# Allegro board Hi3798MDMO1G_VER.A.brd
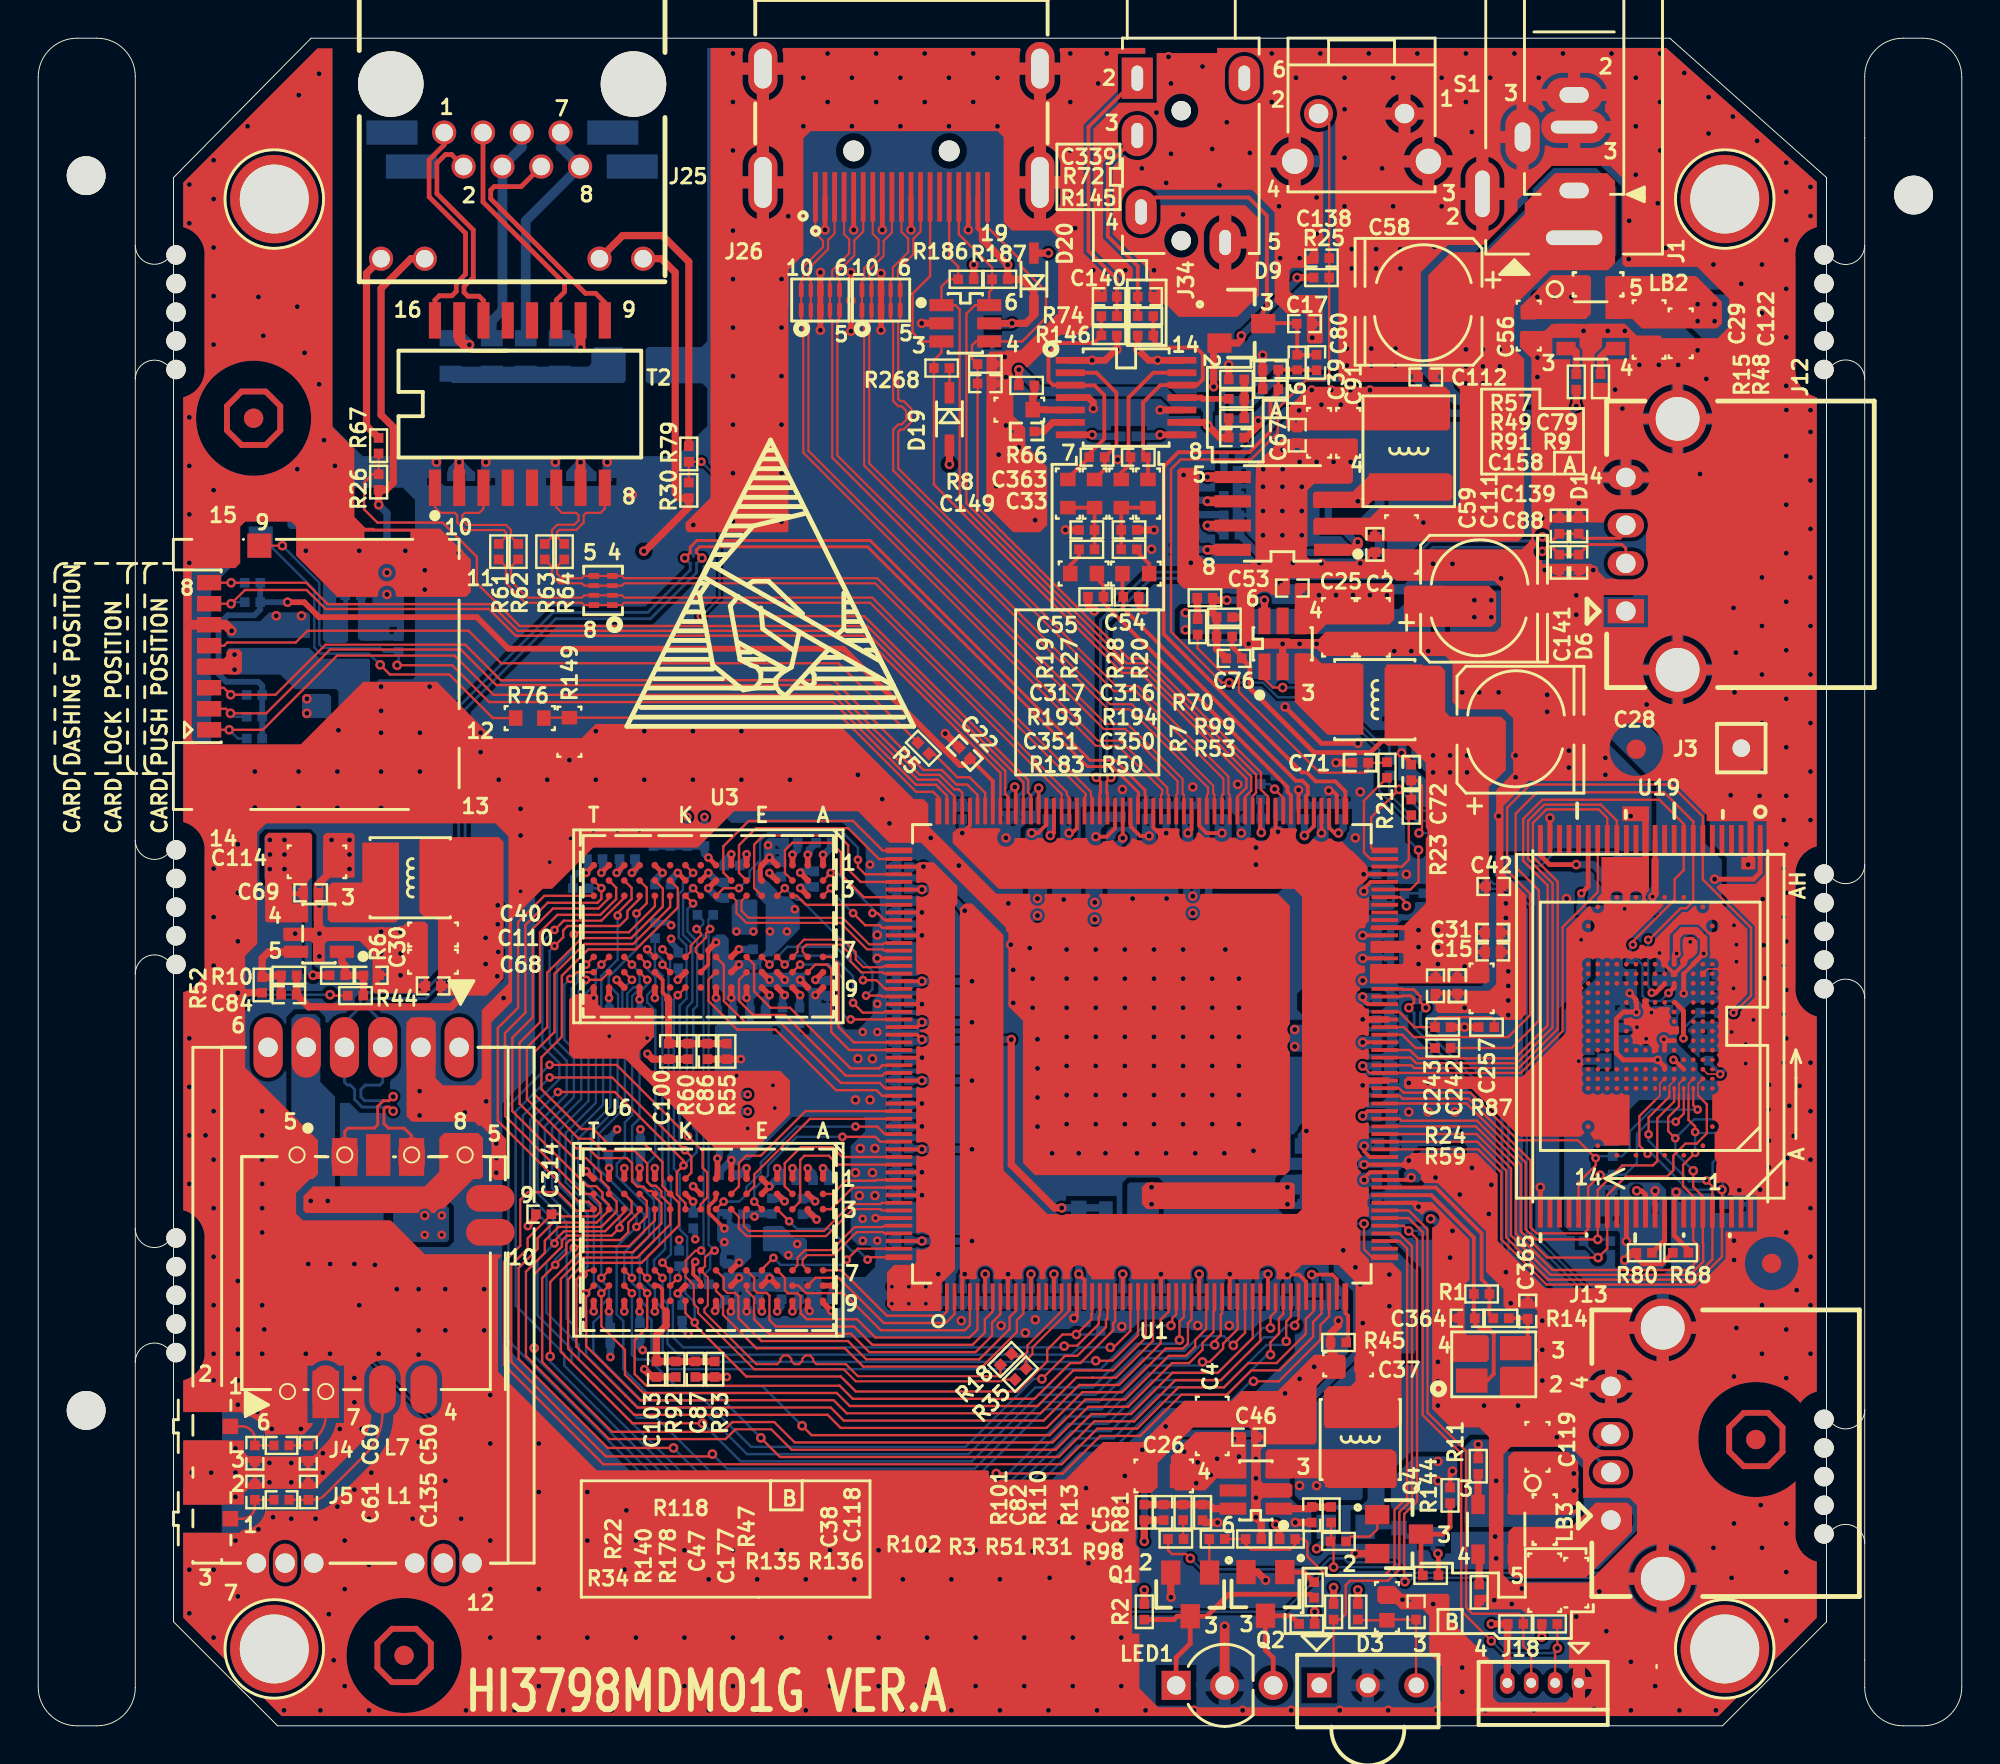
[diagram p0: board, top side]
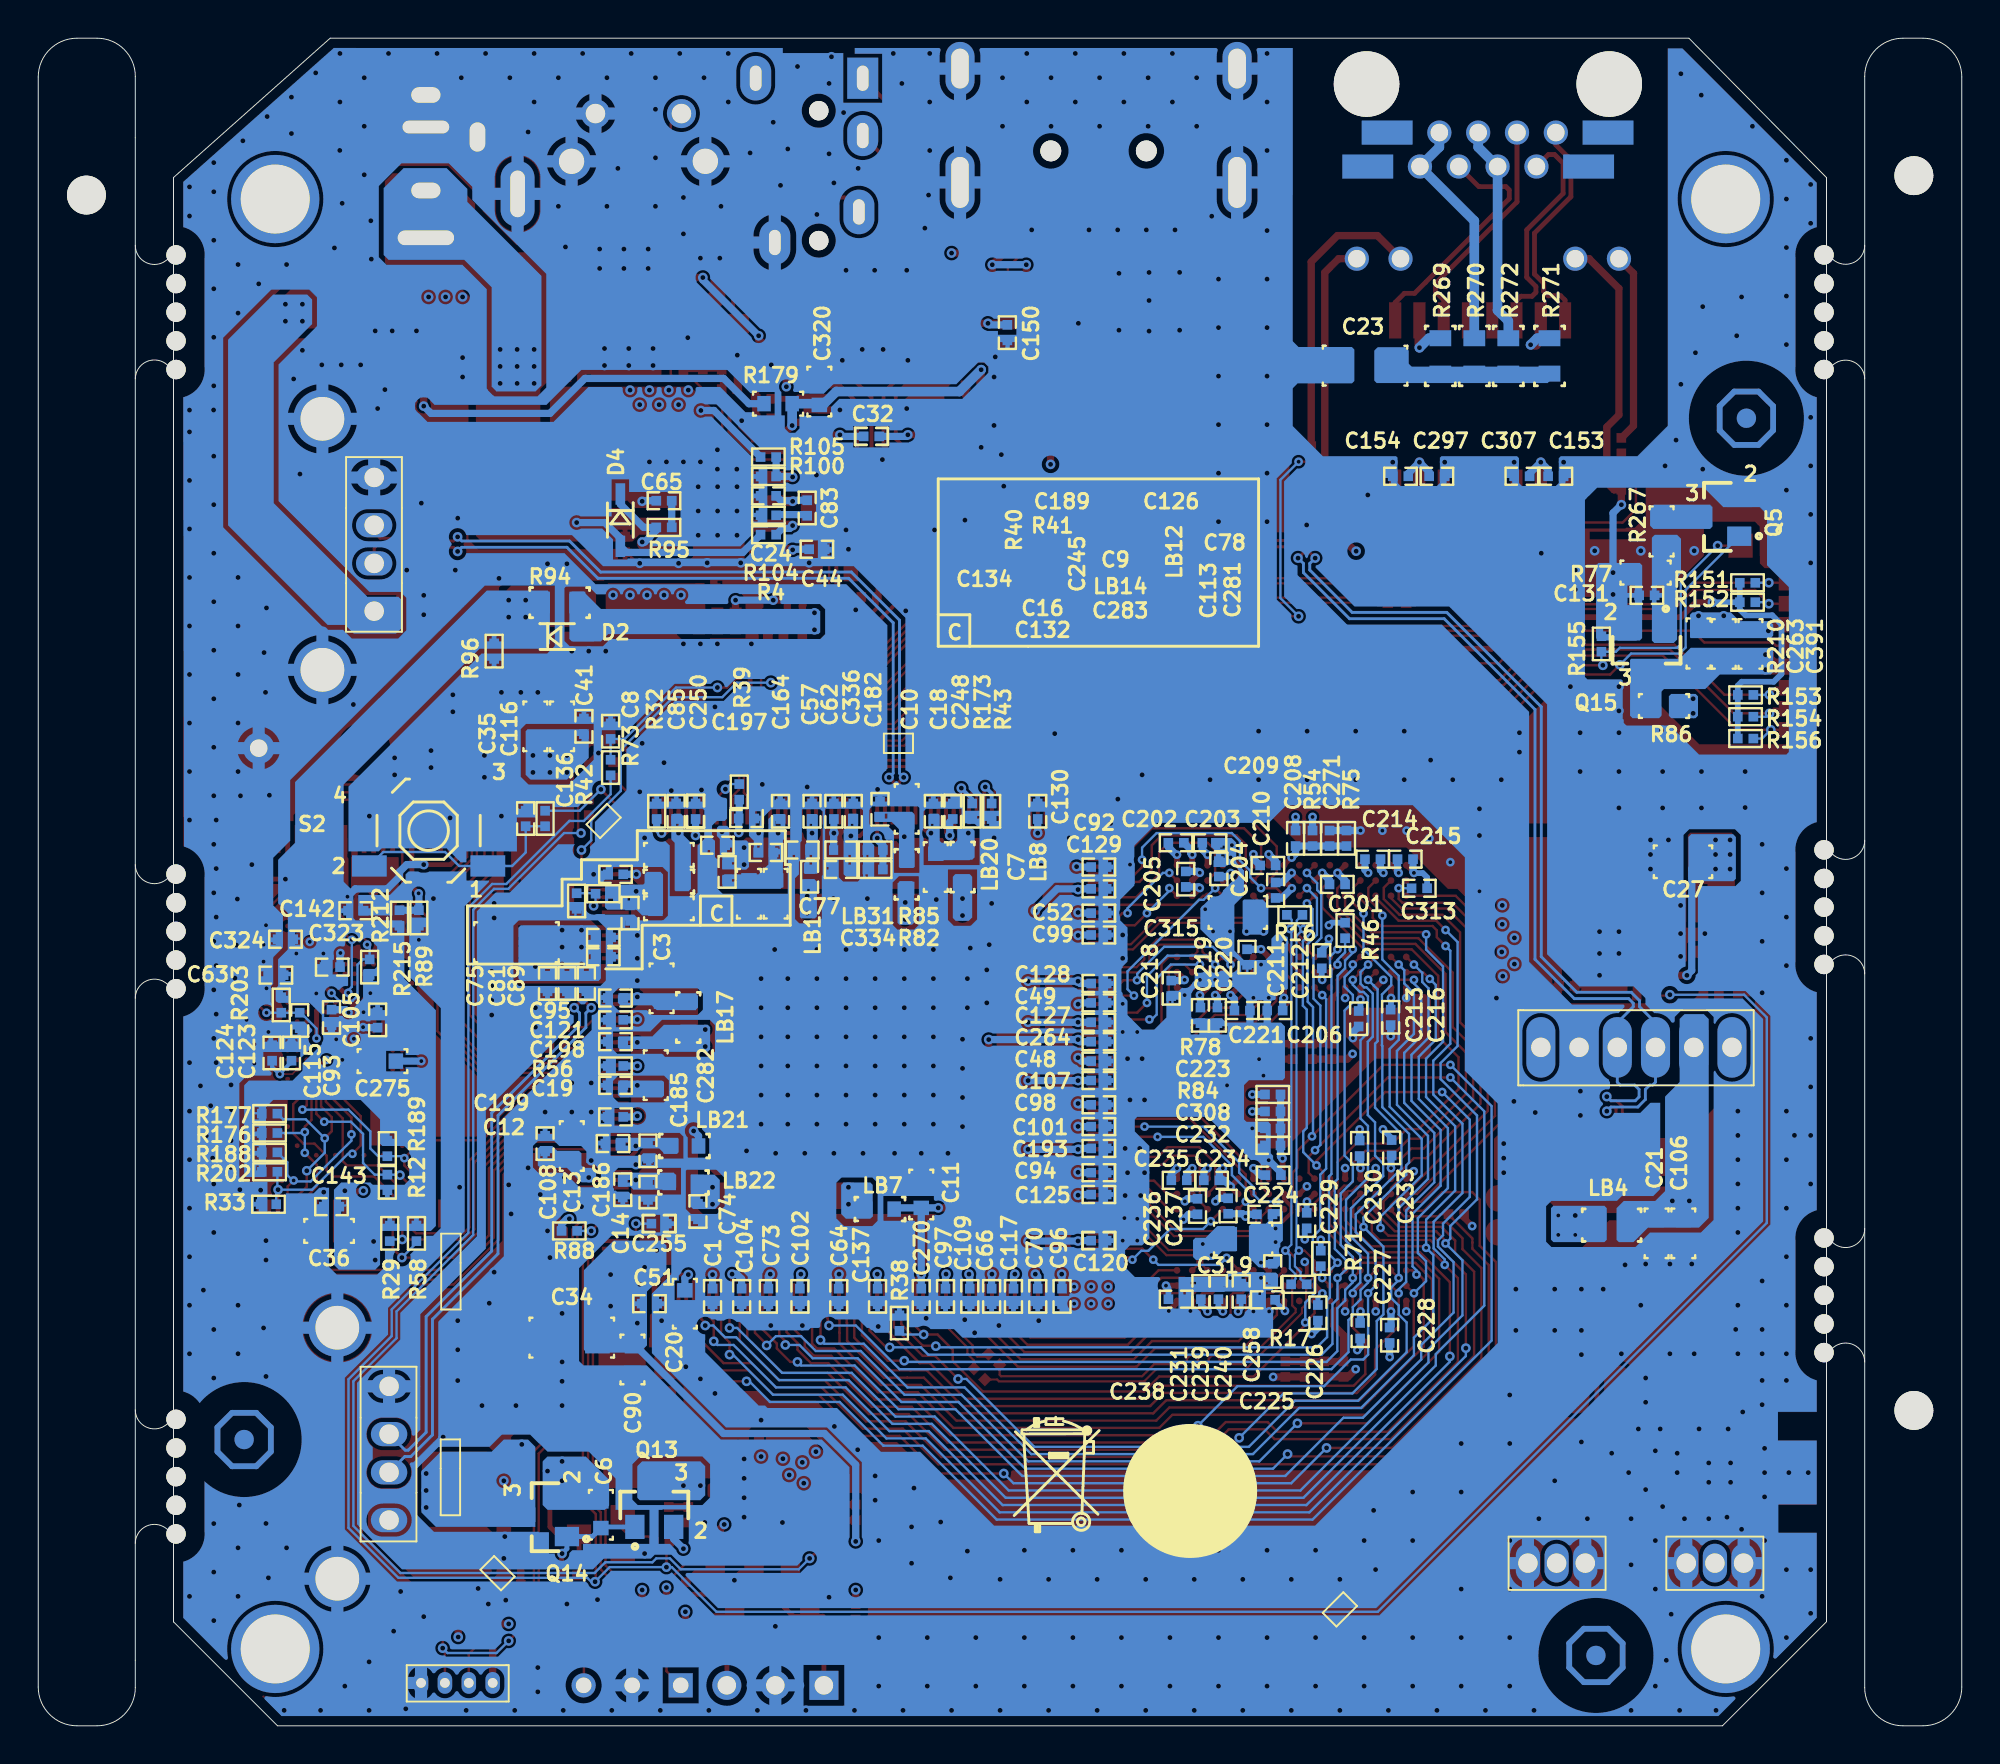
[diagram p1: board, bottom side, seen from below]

Outline 100.66 x 88.35 mm; copper layers: TOP, GND02, POWER03, BOTTOM. Coordinates in mm from the lower left corner of the outline.
Outline path: 0,86.32 0,2.03 arc(0.6,0.6) 2.03,0 3.08,0 arc(4.49,0.59) 5.08,2 5.08,86.35 arc(4.49,87.76) 3.08,88.35 2.03,88.35 arc(0.6,87.75) 0,86.32 ; 7.08,81.05 14.28,88.35 85.38,88.35 93.58,81.05 93.58,5.44 88.14,0 12.53,0 7.08,5.45 7.08,81.05 ; 95.58,86.35 95.58,2 arc(96.17,0.59) 97.58,0 98.63,0 arc(100.06,0.6) 100.66,2.03 100.66,86.32 arc(100.06,87.75) 98.63,88.35 97.58,88.35 arc(96.17,87.76) 95.58,86.35

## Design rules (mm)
constraint set DEFAULT: min track width 0.127
net group 01: nets ADAC_VOUTL ADAC_VOUTR
net group $5N541: nets 5V0 $5N541
net group $5N549: nets $5N549 STANDBY_PWROFF
net group $6N2392: nets $6N2392 NF_REN_EMMC_CLK
net group $16N1187: nets $16N1187 $16N1188
net group $16N1189: nets $16N1189 $16N1190
net group RX+_PHY0: nets RX+_PHY0 RX-_PHY0
net group TX+_PHY0: nets TX+_PHY0 TX-_PHY0
net group USB2_DP: nets USB2_DM USB2_DP
net group 00: nets GND
net group 02: nets 1V1_CPU
net group DDR: nets DDR_ADDR0 DDR_ADDR1 DDR_ADDR2 DDR_ADDR3 DDR_ADDR4 DDR_ADDR5 DDR_ADDR6 DDR_ADDR7 DDR_ADDR8 DDR_ADDR9 DDR_ADDR10 DDR_ADDR11 DDR_ADDR12 DDR_ADDR13 DDR_ADDR14 DDR_ADDR15 DDR_BA0 DDR_BA1 DDR_BA2 DDR_CASN DDR_CKE DDR_CSN DDR_DM0 DDR_DM1 DDR_DM2 DDR_DM3 DDR_DQ0 DDR_DQ1 DDR_DQ2 DDR_DQ3 DDR_DQ4 DDR_DQ5 DDR_DQ6 DDR_DQ7 DDR_DQ8 DDR_DQ9 DDR_DQ10 DDR_DQ11 DDR_DQ12 DDR_DQ13 DDR_DQ14 DDR_DQ15 DDR_DQ16 DDR_DQ17 DDR_DQ18 DDR_DQ19 DDR_DQ20 DDR_DQ21 DDR_DQ22 DDR_DQ23 DDR_DQ24 DDR_DQ25 DDR_DQ26 DDR_DQ27 DDR_DQ28 DDR_DQ29 DDR_DQ30 DDR_DQ31 DDR_ODT DDR_RASN DDR_RESETN DDR_WEN
net group DIFF90: nets USB0_DM USB0_DP USB1_DM USB1_DP
net group DIFF100: nets $8N1926 $8N1927 DDR_CLK0N DDR_CLK0P
net group POWER: nets 1V1_CORE 1V5_DDR3 3V3_MOS
net group VIN: nets 3V3

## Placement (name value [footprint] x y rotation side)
C1  100NF  [SC0402]  65.37 22.48 270 bottom
C2  10UF  [SC0805]  69.87 57.51 270 top
C3  1UF  [SC0603]  68.04 38.61 90 bottom
C4  10UF  [SC0805]  61.44 15.7 90 top
C5  220NF  [SC0402]  66.64 11.05 270 top
C6  220NF  [SC0603]  71.21 11.05 270 bottom
C7  1UF  [SC0603]  53.69 44.96 270 bottom
C8  220NF  [SC0402]  70.71 52.07 90 bottom
C9  1UF  [SC0603]  67.66 45.59 0 bottom
C10  1UF  [SC0603]  55.21 48.01 90 bottom
C11  1UF  [SC0603]  54.45 27.81 90 bottom
C12  1UF  [SC0402]  70.58 30.48 0 bottom
C13  1UF  [SC0603]  72.74 30.35 90 bottom
C14  1UF  [SC0402]  68.75 27.94 270 bottom
C15  100NF  [SC0402]  76.12 40.51 0 top
C16  100NF  [SC0402]  71.09 41.27 180 bottom
C17  180PF  [SC0402]  66.26 73.41 0 top
C18  10NF/NC  [SC0402]  53.82 47.88 90 bottom
C19  470NF  [SC0402]  70.45 33.53 0 bottom
C20  10UF/NC  [SC0603]  66.82 22.1 270 bottom
C21  10UF  [SC0603]  15.97 25.78 270 bottom
C22  2.2UF  [HSC0402]  48.48 50.93 135 top
C23  1NF  [SC1206]  31.23 71.21 0 bottom
C24  47PF/NC  [SC0402]  62.45 64.39 0 bottom
C25  10UF  [SC0805]  68.04 57.51 270 top
C26  10UF/NC  [SC0805]  58.9 13.08 180 top
C27  10UF/NC  [SC0805]  14.59 45.23 0 bottom
C28  100UF  [SAC6666]  77.56 52.15 0 top
C29  22UF  [SC0805]  84.3 73.1 270 top
C30  220NF  [SC0402]  17.43 39.29 0 top
C31  2.2UF  [HSC0402]  76.12 41.53 0 top
C32  330N  [HSC0402]  57.06 67.5 0 bottom
C33  330N  [HSC0402]  51.72 67.76 0 top
C34  47UF/NC  [SC1206]  72.74 20.32 0 bottom
C35  10UF  [SC0603]  74.64 52.32 90 bottom
C36  1UF/NC  [SC0603]  85.44 25.91 0 bottom
C37  10UF  [SC0603]  68.55 18.92 180 top
C38  22UF  [SC0805]  78.83 7.49 270 top
C39  10UF  [SC0603]  67.02 67.69 270 top
C40  10UF  [SC0603]  20.66 41.42 180 top
C41  100NF  [SC0402]  72.1 52.32 90 bottom
C42  100NF  [SC0402]  76.17 43.94 0 top
C44  100NF  [SC0402]  59.91 61.59 180 bottom
C46  100NF  [SC0402]  63.34 15.11 0 top
C47  10UF  [SC0603]  70.58 6.22 90 top
C48  100NF  [SC0402]  45.15 34.8 180 bottom
C49  100NF  [SC0402]  45.15 37.85 180 bottom
C50  1PF/NC  [SC0402]  14.13 14.27 270 top
C51  100NF  [SC0402]  68.67 22.1 180 bottom
C52  100NF  [SC0402]  45.15 42.55 180 bottom
C53  100NF  [SC0402]  65.63 59.56 180 top
C54  47PF  [SC0402]  57.57 66.41 180 top
C55  47PF  [SC0402]  55.41 66.41 180 top
C56  100NF  [SC0603]  78 73.3 270 top
C57  100NF/NC  [SC0402]  60.17 47.88 90 bottom
C58  100UF  [SAC6666]  72.23 74.55 180 top
C59  100NF  [SC0402]  69.94 61.85 270 top
C60  1PF/NC  [SC0402]  11.34 14.27 270 top
C61  1PF/NC  [SC0402]  11.34 12.24 90 top
C62  100NF  [SC0402]  59.02 47.88 90 bottom
C63  100NF/NC  [SC0402]  88.22 39.3 0 bottom
C64  100NF  [SC0402]  58.77 22.48 270 bottom
C65  10NF  [SC0402]  67.91 64.14 0 bottom
C66  100NF  [SC0402]  50.77 22.48 270 bottom
C67  100NF  [SC0402]  65.88 67.56 270 top
C68  100NF/NC  [SC0402]  20.67 38.73 180 top
C69  100NF  [SC0402]  14.26 43.61 0 top
C70  100NF  [SC0402]  48.35 22.48 270 bottom
C71  2.2UF  [HSC0402]  69.18 50.42 180 top
C72  2.2UF  [HSC0402]  71.85 49.91 90 top
C73  100NF  [SC0402]  62.45 22.48 270 bottom
C74  100NF/NC  [SC0402]  66.13 26.92 270 bottom
C75  100NF  [SC0402]  74.01 38.86 270 bottom
C76  22PF  [SC0402]  62.58 55.88 0 top
C77  1UF  [SC0402]  60.67 45.85 0 bottom
C78  100NF/NC  [SC0402]  62.58 45.72 0 bottom
C79  180PF  [SC0402]  64.48 70.99 180 top
C80  100PF  [SC0402]  66.9 71.37 90 top
C81  100NF  [SC0402]  72.99 38.86 270 bottom
C82  22PF  [SC0402]  58.9 11.18 270 top
C83  3.3NF  [SC0402]  60.42 63.75 270 bottom
C84  22PF  [SC0402]  13.12 38.27 0 top
C85  100NF/NC  [SC0402]  67.28 47.88 90 bottom
C86  100NF  [SC0402]  35.02 35.31 270 top
C87  100NF  [SC0402]  34.38 18.67 270 top
C88  100UF/NC  [SAC6666]  75.66 59 0 top
C89  100NF  [SC0402]  71.98 38.86 270 bottom
C90  10UF  [SC0603]  69.56 19.18 270 bottom
C91  10UF  [SC0603]  68.55 67.69 270 top
C92  1UF  [SC0402]  45.15 44.96 180 bottom
C93  100NF/NC  [SC0402]  85.31 37.08 90 bottom
C94  1UF/NC  [SC0402]  45.15 28.96 180 bottom
C95  100NF/NC  [SC0402]  70.45 38.1 0 bottom
C96  1UF  [SC0402]  47.08 22.48 270 bottom
C97  470NF  [SC0402]  53.18 22.48 270 bottom
C98  100NF  [SC0402]  45.15 32.51 180 bottom
C99  100NF/NC  [SC0402]  45.15 41.4 180 bottom
C100  100NF  [SC0402]  32.99 35.31 90 top
C101  100NF  [SC0402]  45.15 31.37 180 bottom
C102  100NF  [SC0402]  60.8 22.48 270 bottom
C103  100NF  [SC0402]  32.35 18.67 90 top
C104  100NF  [SC0402]  63.85 22.48 270 bottom
C105  100NF  [SC0402]  82.9 36.96 270 bottom
C106  100NF  [SC0603]  14.57 25.78 270 bottom
C107  100NF  [SC0402]  45.15 33.78 180 bottom
C108  100NF/NC  [SC0402]  74.14 30.48 90 bottom
C109  470NF  [SC0402]  51.91 22.48 270 bottom
C110  10UF  [SC0603]  20.66 40 180 top
C111  10UF  [SC0805]  71.34 61.85 270 top
C112  100NF  [SC0402]  72.61 70.61 180 top
C113  2.2UF/NC  [SC0603]  63.47 43.56 270 bottom
C114  10UF  [SC0805]  14.59 45.23 0 top
C115  1NF/NC  [SC0402]  86.98 36.92 270 bottom
C116  10UF  [SC0603]  73.25 52.32 90 bottom
C117  470NF  [SC0402]  49.62 22.48 270 bottom
C118  100NF/NC  [SC0603]  80.49 7.49 270 top
C119  100NF  [SC0603]  78.45 14.61 90 top
C120  2.2UF  [HSC0402]  45.15 25.4 180 bottom
C121  100NF  [SC0402]  70.45 36.96 0 bottom
C122  100NF/NC  [SC0603]  85.95 72.9 270 top
C123  100NF  [SC0402]  87.41 35.22 90 bottom
C124  100NF  [SC0402]  88.42 35.22 90 bottom
C125  100NF/NC  [SC0402]  45.15 27.81 180 bottom
C126  100NF  [SC0402]  65.12 46.1 0 bottom
C127  100NF  [SC0402]  45.15 36.83 180 bottom
C128  100NF  [SC0402]  45.15 38.86 180 bottom
C129  100NF  [SC0402]  45.15 43.81 180 bottom
C130  100NF  [SC0402]  48.35 47.88 90 bottom
C131  1UF/NC  [SC0402]  16.48 59.18 180 bottom
C132  1UF  [SC0402]  71.09 40.26 180 bottom
C134  22UF/NC  [SC1206]  75.63 41.02 0 bottom
C135  1PF/NC  [SC0402]  14.14 12.24 90 top
C136  100NF  [SC0402]  75.15 47.5 90 bottom
C137  100NF  [SC0402]  56.74 22.48 270 bottom
C138  100NF  [SC0402]  67.15 76.83 0 top
C139  3PF  [SC0402]  79.6 62.81 90 top
C140  1NF  [SC0402]  56.04 74.82 180 top
C141  3PF  [SC0402]  79.6 60.91 270 top
C142  100NF/NC  [SC0402]  84.04 42.67 180 bottom
C143  100NF/NC  [SC0402]  85.31 27.18 0 bottom
C149  100NF  [SC0402]  49.56 70.27 0 top
C150  100NF  [SC0402]  49.95 72.93 270 bottom
C153  100NF  [SC0402]  21.24 65.42 180 bottom
C154  100NF  [SC0402]  29.37 65.42 0 bottom
C158  100NF  [SC0402]  62.71 67.44 0 top
C164  10NF  [SC0402]  61.82 47.88 90 bottom
C177  100NF/NC  [SC0402]  72.1 5.97 90 top
C182  10NF/NC  [SC0402]  56.61 47.98 90 bottom
C185  10NF  [SC0402]  68.75 30.1 270 bottom
C186  10NF  [SC0402]  70.07 28.07 270 bottom
C189  1UF  [SC0402]  70.45 44.58 0 bottom
C193  1UF  [SC0402]  45.15 30.23 180 bottom
C197  100NF  [SC0402]  63.59 47.5 180 bottom
C198  100NF  [SC0402]  70.45 35.81 0 bottom
C199  100NF  [SC0402]  70.45 31.88 0 bottom
C201  100NF/NC  [SC0402]  32.68 44.05 180 bottom
C202  100NF/NC  [SC0402]  41.12 46.23 180 bottom
C203  100NF/NC  [SC0402]  39.34 46.23 180 bottom
C204  100NF  [SC0402]  38.88 44.86 90 bottom
C205  100NF/NC  [SC0402]  40.61 44.32 270 bottom
C206  100NF/NC  [SC0402]  35.94 37.44 0 bottom
C208  100NF  [SC0402]  34.86 46.46 270 bottom
C209  100NF/NC  [SC0402]  36.31 45.04 180 bottom
C210  100NF/NC  [SC0402]  35.9 43.75 90 bottom
C211  100NF  [SC0402]  37.4 40.25 270 bottom
C212  100NF  [SC0402]  33.49 40.06 90 bottom
C213  100NF  [SC0402]  31.56 37.01 270 bottom
C214  100NF  [SC0402]  30.82 45.37 180 bottom
C215  100NF/NC  [SC0402]  29.12 45.37 180 bottom
C216  100NF/NC  [SC0402]  29.89 37.09 270 bottom
C218  100NF/NC  [SC0402]  41.37 38.61 270 bottom
C219  100NF/NC  [SC0402]  39.84 37.19 270 bottom
C220  100NF/NC  [SC0402]  38.95 37.19 270 bottom
C221  100NF  [SC0402]  37.66 37.45 180 bottom
C223  100NF  [SC0402]  36.06 32.16 180 bottom
C224  100NF/NC  [SC0402]  36.48 26.78 0 bottom
C225  100NF/NC  [SC0402]  36.34 22.3 0 bottom
C226  100NF/NC  [SC0402]  33.7 21.62 270 bottom
C227  100NF  [SC0402]  31.49 20.68 270 bottom
C228  100NF/NC  [SC0402]  29.94 20.45 270 bottom
C229  100NF  [SC0402]  34.28 26.45 270 bottom
C230  100NF  [SC0402]  31.51 30.23 90 bottom
C231  100NF/NC  [SC0402]  39.82 22.74 90 bottom
C232  100NF/NC  [SC0402]  36.04 28.83 180 bottom
C233  100NF/NC  [SC0402]  29.83 30.26 90 bottom
C234  100NF/NC  [SC0402]  39.26 28.56 180 bottom
C235  100NF/NC  [SC0402]  40.96 28.56 180 bottom
C236  100NF/NC  [SC0402]  39.99 27.18 270 bottom
C237  100NF  [SC0402]  38.39 27.21 270 bottom
C238  100NF/NC  [SC0402]  41.11 22.33 180 bottom
C239  100NF  [SC0402]  38.9 22.74 90 bottom
C240  100NF/NC  [SC0402]  37.71 22.74 90 bottom
C242  2.2UF  [HSC0402]  74.26 38.73 270 top
C243  470NF  [SC0402]  73.12 38.73 270 top
C245  100NF  [SC0402]  69.69 42.55 270 bottom
C248  2.2UF  [HSC0402]  52.8 47.88 90 bottom
C250  2.2UF  [HSC0402]  66.26 47.88 270 bottom
C255  2.2UF  [HSC0402]  68.17 26.29 0 bottom
C257  10UF  [SC0603]  75.53 38.61 270 top
C258  100NF  [SC0402]  36.06 23.78 270 bottom
C263  100NF  [SC0603]  12.46 56.64 90 bottom
C264  10NF/NC  [SC0402]  45.15 35.81 180 bottom
C270  10NF  [SC0402]  54.45 22.48 270 bottom
C271  100NF  [SC0402]  33.09 46.46 90 bottom
C275  2.2UF  [SC0603]  82.64 34.8 180 bottom
C281  10UF  [SC0603]  62.07 43.56 270 bottom
C282  10UF  [SC0603]  68.34 34.06 90 bottom
C283  2.2UF  [SC0603]  67.66 42.8 180 bottom
C297  10NF/NC  [SC0402]  27.47 65.42 180 bottom
C307  10NF/NC  [SC0402]  23.02 65.42 0 bottom
C308  100NF  [SC0402]  36.06 30.39 0 bottom
C313  1NF  [SC0402]  28.39 43.85 180 bottom
C314  1NF  [SC0402]  26.45 26.78 180 top
C315  10UF/NC  [SC0805]  37.89 42.58 0 bottom
C316  680PF  [SC0402]  57.08 62.6 0 top
C317  680PF  [SC0402]  54.87 62.6 180 top
C319  10UF/NC  [SC0805]  37.61 25.48 0 bottom
C320  10UF  [SC0603]  59.78 69.85 90 bottom
C323  100NF/NC  [SC0402]  85.27 39.72 180 bottom
C324  100NF/NC  [SC0402]  87.72 41.18 0 bottom
C334  1UF  [SC0402]  58.64 44.83 0 bottom
C336  10NF/NC  [SC0402]  58.01 47.88 90 bottom
C339  1NF  [SC0402]  57.95 74.82 0 top
C350  2.2UF  [SC0603]  57.44 60.32 180 top
C351  2.2UF  [SC0603]  54.7 60.33 180 top
C363  10UF/NC  [SC0603]  51.34 68.9 180 top
C364  30PF  [SC0402]  74.77 21.34 180 top
C365  30PF  [SC0402]  77.95 21.72 90 top
C391  2.2UF  [SC0603]  11.06 56.64 90 bottom
D1  NC  [SC0402]  80.61 62.81 90 top
D2  NC  [HSOD323A]  73.5 57.02 0 bottom
D3  IR  [SEN3-100C]  69.58 2.12 0 top
D4  NC  [HSOD323A]  70.2 63.12 90 bottom
D6  NC  [SC0402]  80.61 60.91 270 top
D9  D2-3_A  [SOT23]  62.96 73.41 270 top
D19  D_A  [HSOD323A]  47.68 68.41 90 top
D20  D_A  [HSOD323A]  52.1 75.73 270 top
ID1  PCB_MARKPOINT_A  [ID-BOARD]  11.27 68.45 180 bottom
ID2  PCB_MARKPOINT_A  [ID-BOARD]  89.88 14.99 180 bottom
ID3  PCB_MARKPOINT_A  [ID-BOARD]  19.14 3.68 180 bottom
ID4  PCB_MARKPOINT_A  [ID-BOARD]  11.27 68.45 0 top
ID5  PCB_MARKPOINT_A  [ID-BOARD]  19.14 3.68 0 top
ID6  PCB_MARKPOINT_A  [ID-BOARD]  89.88 14.99 0 top
J1  DC_012_HW  [PWC3-RF-A]  80.37 77.9 90 top
J2  WIFI_2T2R  [SIP12-2_0MM-1827]  17.02 22.02 270 top
J3  NC  [SIP-1P]  89.12 51.18 0 top
J4  NC  [HSCOX-AMC-TM-A]  8.7 15.68 270 top
J5  NC  [HSCOX-AMC-TM-A]  8.7 10.84 270 top
J10  NC  [DC-002]  80.37 80.38 0 top
J12  SMDUSBA  [USB4-1415]  83.08 58.35 90 top
J13  SMDUSBA  [USB4-1415]  82.3 10.77 90 top
J18  SDW12501_4A_HW  [WBC0104-49T]  80.63 2.24 180 top
J21  5031820832  [MICRO_SD8-PUSH]  14.55 55.04 270 top
J25  406533_1  [MJ8-RLY]  21.24 83.41 0 top
J26  0  [WBC0119-20R-A]  45.17 85.19 180 top
J34  8967_3506ADT_M_A  [VAF6-1107]  57.51 86.25 270 top
L1  1NH/NC  [SL0402]  12.73 11.83 0 top
L2  3.3UH  [SWPA4020S]  69.94 53.72 0 top
L3  3.3UH  [SWPA4020S]  69.18 14.99 90 top
L4  3.3UH  [SWPA4020S]  19.47 44.39 0 top
L5  6.8UH  [SWPA5040S]  71.72 66.73 90 top
L6  220NH  [SL0402]  65.88 71.37 90 top
L7  1NH/NC  [SL0402]  12.73 14.68 0 top
LB1  0  [SL0402]  60.29 44.45 270 bottom
LB2  NC  [SL0603]  81.63 75.46 180 top
LB3  NC  [SL0603]  78.83 10.79 90 top
LB4  MGLB2012_220T_LF  [SL0805]  18.32 26.21 0 bottom
LB7  0  [SL0603]  56.61 27.05 0 bottom
LB8  0  [SL0603]  52.29 44.96 270 bottom
LB12  BLM15HG102SN1D  [SL0402]  64.61 44.7 90 bottom
LB14  0  [SL0603]  67.66 44.2 180 bottom
LB17  0  [SL0603]  66.64 37.08 90 bottom
LB20  0  [SL0603]  55.21 44.58 90 bottom
LB21  0  [SL0603]  66.85 30.35 0 bottom
LB22  0  [SL0603]  66.9 28.45 0 bottom
LB31  0  [SL0402]  58.64 45.85 180 bottom
LED1  209_3SYGSURC_S530_A3HW  [LED3C-100C]  59.55 2.12 0 top
M20  M3_HOLE_A  [HOLE182-142]  88.26 4.02 0 top
M21  M3_HOLE_A  [HOLE182-142]  12.35 4.02 0 top
M22  M3_HOLE_A  [HOLE182-142]  88.26 79.93 0 top
M23  M3_HOLE_A  [HOLE182-142]  12.35 79.93 0 top
NOREF  -  [unnamed]  94.58 74 90 top
NOREF#2  -  [unnamed]  94.58 13.04 90 top
NOREF#3  -  [unnamed]  6.08 74 270 top
NOREF#4  -  [#2]  51.99 192.84 0 top
NOREF#5  -  [#2]  7.08 8.64 0 top
NOREF#6  -  [#2]  0 7.94 0 top
NOREF#7  -  [unnamed]  94.58 41.59 90 top
NOREF#8  -  [#2]  34.38 141.53 0 top
NOREF#9  -  [unnamed]  6.08 22.54 270 top
NOREF#10  -  [#2]  101.57 88.65 0 top
NOREF#11  -  [unnamed#3]  2.51 16.51 0 top
NOREF#12  -  [unnamed#3]  98.14 80.14 0 top
NOREF#13  -  [#2]  16.48 0 90 top
NOREF#14  -  [#2]  206.52 186.74 0 top
NOREF#15  -  [#2]  135.72 142.52 180 top
NOREF#16  -  [unnamed]  6.08 42.86 270 top
NOREF#17  -  [#2]  -171.74 -149.53 0 top
NOREF#18  -  [#2]  38.83 56.77 0 top
NOREF#19  -  [unnamed#3]  2.51 81.15 0 top
NOREF#20  -  [#2]  44.82 13.23 180 bottom
NOREF#21  -  [#2]  39.87 12.52 180 bottom
Q1  NPN-BEC  [SOT23]  60.28 6.88 180 top
Q2  NPN-BEC  [SOT23]  64.22 6.9 180 top
Q4  NPN-BEC  [SOT23]  71.21 10.03 270 top
Q5  /NC  [SOT23]  12.79 63.29 90 bottom
Q13  PMOS-GSD  [SOT23]  68.42 11.56 180 bottom
Q14  PMOS-GSD  [SOT23]  74.14 10.92 90 bottom
Q15  /NC  [SOT23]  16.5 56.31 0 bottom
R1  1MEG  [SR0402]  75.53 22.61 180 top
R2  330  [SR0402]  57.88 5.97 270 top
R3  1K  [SR0402]  61.69 9.78 180 top
R4  100K  [SR0402]  62.45 62.36 180 bottom
R5  22  [SR0402]  46.32 51.18 135 top
R6  47K  [SR0402]  15.66 39.29 0 top
R7  51K  [SR0402]  60.67 57.53 270 top
R8  47K  [SR0402]  49.56 71.28 180 top
R9  75  [SR0402]  64.48 69.98 180 top
R10  150K  [SR0402]  13.12 39.29 0 top
R11  10K  [SR0402]  75.36 13.59 90 top
R12  47K  [SR0402]  82.39 28.45 90 bottom
R13  13.7K  [SR0402]  60.93 11.18 90 top
R14  0  [SR0402]  76.55 21.34 0 top
R15  10K  [SR0402]  80.49 70.36 270 top
R16  200  [SR0402]  34.91 42.45 180 bottom
R17  200  [SR0402]  34.69 23.11 180 bottom
R18  0  [SR0402]  50.64 19.18 45 top
R19  75K  [SR0603]  53.88 64.51 90 top
R20  75K  [SR0603]  58.07 64.51 270 top
R21  1K  [SR0402]  70.58 50.04 270 top
R22  10K  [SR0402]  66.77 7.11 90 top
R23  1K  [SR0402]  71.85 48.08 270 top
R24  270  [SR0402]  73.5 36.58 180 top
R25  1K  [SR0402]  67.15 75.82 0 top
R26  4.7K  [SR0402]  17.81 65.11 90 top
R27  5.1K  [SR0603]  55.28 64.51 90 top
R28  5.1K  [SR0603]  56.68 64.51 270 top
R29  47K  [SR0402]  82.26 25.78 270 bottom
R30  4.7K  [SR0402]  34.04 64.68 90 top
R31  4.7K/NC  [SR0402]  65.37 9.78 0 top
R32  12K  [SR0402]  68.29 47.88 270 bottom
R33  10K/NC  [SR0402]  88.61 27.3 0 bottom
R34  330  [SR0402]  66.39 5.33 180 top
R35  0  [SR0402]  51.4 18.41 45 top
R38  10K/NC  [SR0402]  55.59 21.08 270 bottom
R39  10K  [SR0402]  63.98 48.9 270 bottom
R40  10K/NC  [SR0402]  72.48 43.18 270 bottom
R41  10K  [SR0402]  71.09 43.56 180 bottom
R42  1K  [SR0402]  74.14 47.5 90 bottom
R43  10K  [SR0402]  50.77 47.88 270 bottom
R44  20K/NC  [SR0402]  16.6 38.23 0 top
R45  240  [SR0402]  68.04 20.07 180 top
R46  240  [SR0402]  32.27 41.64 270 bottom
R47  22K  [SR0402]  75.41 6.99 90 top
R48  22K  [SR0402]  81.76 70.36 90 top
R49  0  [SR0402]  62.71 69.47 0 top
R50  470K  [SR0402]  57.18 59.1 0 top
R51  4.7K  [SR0402]  63.59 9.78 0 top
R52  100K  [SR0402]  11.72 38.78 270 top
R53  15K  [SR0402]  62.07 57.02 0 top
R54  1K  [SR0402]  33.97 46.46 270 bottom
R55  1K  [SR0402]  36.04 35.31 270 top
R56  10K  [SR0402]  70.45 34.54 180 bottom
R57  2.2K  [SR0402]  62.71 70.48 180 top
R58  47K  [SR0402]  80.87 25.78 270 bottom
R59  75  [SR0402]  73.5 35.48 180 top
R60  1K  [SR0402]  34 35.31 90 top
R61  10  [SR0402]  24.1 61.47 90 top
R62  10  [SR0402]  25.11 61.47 90 top
R63  10  [SR0402]  26.51 61.47 90 top
R64  10  [SR0402]  27.53 61.47 90 top
R66  470K  [SR0402]  51.72 70.17 180 top
R67  330  [SR0402]  17.81 67.02 270 top
R68  0/NC  [SR0402]  85.95 24.77 180 top
R70  33K  [SR0402]  61.05 59.05 180 top
R71  240  [SR0402]  33.54 24.47 270 bottom
R72  560  [HSR0402]  57.95 73.8 180 top
R73  20K  [SR0402]  70.71 50.16 90 bottom
R74  560  [HSR0402]  56.04 73.8 180 top
R75  1K  [SR0402]  32.2 46.46 90 bottom
R76  10K/NC  [SR0603]  25.72 52.76 180 top
R77  10K/NC  [SR0603]  16.55 60.37 180 bottom
R78  1K  [SR0402]  36.06 33.05 180 bottom
R79  330  [SR0402]  34.04 66.58 270 top
R80  0/NC  [SR0402]  84.04 24.77 0 top
R81  20K  [SR0402]  67.66 11.05 90 top
R82  270  [SR0402]  56.86 44.83 180 bottom
R84  1K  [SR0402]  36.06 31.27 0 bottom
R85  270  [SR0402]  56.86 45.85 180 bottom
R86  0  [SR0603]  15.58 53.39 0 bottom
R87  270  [SR0402]  75.79 36.58 0 top
R88  1K  [SR0402]  72.87 25.91 0 bottom
R89  1K/NC  [SR0402]  80.74 42.29 270 bottom
R91  5.6K  [SR0402]  62.71 68.45 0 top
R92  1K  [SR0402]  33.37 18.67 90 top
R93  1K  [SR0402]  35.4 18.67 270 top
R94  0  [SR0805]  73.37 58.8 0 bottom
R95  0  [SR0402]  67.91 62.74 180 bottom
R96  2K/NC  [SR0402]  76.8 56.26 90 bottom
R98  10K  [SR0402]  68.04 9.65 0 top
R99  11.3K  [SR0402]  62.07 58.04 180 top
R100  10K  [SR0402]  62.45 65.41 0 bottom
R101  14.7K  [SR0402]  57.88 11.18 270 top
R102  100K  [SR0402]  59.53 9.78 180 top
R104  5.6K  [SR0402]  62.45 63.37 0 bottom
R105  26.1K  [SR0402]  62.45 66.42 0 bottom
R110  14.7K  [SR0402]  59.91 11.18 270 top
R118  100K  [SR0402]  72.87 7.87 180 top
R135  10K  [SR0402]  77.31 5.33 0 top
R136  10K  [SR0402]  79.09 5.33 0 top
R140  10K  [SR0402]  67.79 5.97 90 top
R144  4.7K  [SR0402]  73.88 12.06 270 top
R145  100K/NC  [SR0402]  57.95 72.78 180 top
R146  100K/NC  [SR0402]  56.04 72.78 0 top
R149  4.7K/NC  [SR0603]  27.8 52.04 270 top
R151  47K  [SR0402]  11.21 59.84 180 bottom
R152  47K  [SR0402]  11.21 58.82 180 bottom
R153  47K  [SR0402]  11.31 53.97 180 bottom
R154  47K  [SR0402]  11.31 52.83 180 bottom
R155  47K  [SR0402]  18.86 56.64 270 bottom
R156  47K  [SR0402]  11.31 51.68 180 bottom
R173  10K  [SR0402]  51.78 47.88 270 bottom
R176  47K  [SR0402]  88.55 31.03 180 bottom
R177  47K  [SR0402]  88.55 32.05 180 bottom
R178  75  [SR0402]  69.06 5.97 90 top
R179  10  [SR0603]  61.94 69.22 180 bottom
R183  470K  [SR0402]  55.34 59.11 180 top
R186  2K  [SR0402]  48.55 75.73 0 top
R187  2K  [SR0402]  50.33 75.73 0 top
R188  47K  [SR0402]  88.55 30.02 180 bottom
R189  47K  [SR0402]  82.39 30.23 270 bottom
R193  20K  [SR0402]  54.87 61.59 0 top
R194  20K  [SR0402]  57.08 61.59 0 top
R202  47K  [SR0402]  88.55 29 180 bottom
R203  47K  [SR0402]  87.94 37.74 270 bottom
R210  1K/NC  [SR0603]  13.78 56.66 90 bottom
R212  10K  [SR0402]  83.32 39.72 90 bottom
R215  4.7K/NC  [SR0402]  81.76 42.29 90 bottom
R267  100/NC  [SR0603]  15.71 62.53 90 bottom
R268  27K  [SR0402]  47.28 71.08 180 top
R269  75  [SR0805]  27.29 71.72 90 bottom
R270  75  [SR0805]  25.51 71.72 90 bottom
R271  75  [SR0805]  21.57 71.72 90 bottom
R272  75  [SR0805]  23.73 71.72 90 bottom
S1  MS-156  [TSW4-RG-C]  71.5 84.4 180 top
S2  TMG_533_T_R  [SPSW6-T]  80.23 46.86 0 bottom
T2  H1102T  [STFM16-50-285]  25.21 69.19 0 top
U1  HI3798MV100  [LQFP216-040-2424]  57.75 35.18 0 top
U2  NC  [CDTWIFI]  17.55 23.69 90 top
U3  H5TQ4G63MFR_PBC_A  [BGA96-32-1609I]  35.07 41.85 180 top
U4  ESD5305F_CS0806U  [SOT23A-6L]  48.52 73.42 270 top
U5  DIO2103_SGM8903  [SGM8903]  56.93 69.54 270 top
U6  H5TQ4G63MFR_PBC_A  [BGA96-32-1609I]  35.07 25.44 180 top
U7  NC  [CDTWIFI10]  17.16 23.71 90 top
U8  NC  [RN8-0402]  29.56 59.44 90 top
U10  ETA6010  [SOT23-5]  81.25 73.05 270 top
U11  SY8032  [SOT23_6]  65.12 56.64 0 top
U12  ETA6010  [SOT23-5]  76.29 10.29 180 top
U13  SY8032  [SOT23_6]  63.72 12.32 90 top
U14  MP1484_ETA1486  [SOIC8N]  65.11 63.47 90 top
U15  SY8089A_ETA3409  [SOT23_5]  14.69 41.47 90 top
U19  NC  [SOP48-20-720B]  84.36 36.62 180 top
U22  EMMC  [BGA169-BGA153-0_5MM]  84.36 36.62 90 top
U23  ESD5304D_CS0806S  [DFN2510P10E]  40.93 74.64 0 top
U24  ESD5304D_CS0806S  [DFN2510P10E]  44.11 74.64 0 top
X2  24MHZ  [X288]  76.17 18.92 0 top

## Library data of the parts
C1 C5 C8 C12 C14-C19 C24 C30 C41 C42 C44 C46 C48-C55 C57 C59-C70 C73-C87 C89 C92-C105 C107-C109 C112 C115 C117 C121 C123-C132 C135-C143 C149 C150 C153 C154 C158 C177 C182 C185 C186 C189 C193 C197-C199 C201-C206 C208-C216 C218-C221 C223-C240 C243 C245 C258 C264 C270 C271 C297 C307 C308 C313 C314 C316 C317 C323 C324 C334 C336 C339 C364 C365 D1 D6 = SC0402
C2 C4 C25-C27 C29 C38 C111 C114 C315 C319 = SC0805
C3 C6 C7 C9-C11 C13 C20 C21 C35-C37 C39 C40 C47 C56 C90 C91 C106 C110 C113 C116 C118 C119 C122 C257 C263 C275 C281-C283 C320 C350 C351 C363 C391 = SC0603
C22 C31-C33 C71 C72 C120 C242 C248 C250 C255 = HSC0402
C23 C34 C134 = SC1206
C28 C58 C88 = SAC6666
C164 = SC0402: signal model: SC0402_10PF/NC
D2 D4 D19 D20 = HSOD323A
D3 = SEN3-100C
D9 Q1 Q2 Q4 Q5 Q13-Q15 = SOT23
ID1-ID6 = ID-BOARD
J1 = PWC3-RF-A
J2 = SIP12-2_0MM-1827
J3 = SIP-1P
J4 J5 = HSCOX-AMC-TM-A
J10 = DC-002
J12 J13 = USB4-1415
J18 = WBC0104-49T
J21 = MICRO_SD8-PUSH
J25 = MJ8-RLY
J26 = WBC0119-20R-A
J34 = VAF6-1107
L1 L6 L7 LB1 LB12 LB31 = SL0402
L2-L4 = SWPA4020S
L5 = SWPA5040S
LB2 LB3 LB7 LB8 LB14 LB17 LB20-LB22 = SL0603
LB4 = SL0805
LED1 = LED3C-100C
M20-M23 = HOLE182-142
R1-R18 R21-R26 R30-R35 R39-R44 R47-R53 R55-R57 R60-R64 R66-R68 R70 R71 R73 R75 R78-R82 R84 R85 R87-R89 R91-R93 R95 R96 R99-R102 R104 R105 R110 R118 R145 R146 R151-R156 R173 R176 R177 R183 R186-R189 R193 R194 R202 R203 R212 R268 = SR0402
R19 R20 R27 R28 R76 R77 R86 R149 R179 R210 R267 = SR0603
R29 R178 = SR0402: signal model: SR0402_75
R38 R45 R46 = SR0402: signal model: SR0402_33
R54 = SR0402: signal model: SR0402_240
R58 R98 R135 R136 R140 = SR0402: signal model: SR0402_10K
R59 = SR0402: signal model: SR0402_0/NC
R72 R74 = HSR0402
R94 R269-R272 = SR0805
R144 R215 = SR0402: signal model: SR0402_4.7K
S1 = TSW4-RG-C
S2 = SPSW6-T
T2 = STFM16-50-285
U1 = LQFP216-040-2424
U2 = CDTWIFI
U3 U6 = BGA96-32-1609I
U4 = SOT23A-6L
U5 = SGM8903
U7 = CDTWIFI10
U8 = RN8-0402
U10 U12 = SOT23-5
U11 U13 = SOT23_6
U14 = SOIC8N
U15 = SOT23_5
U19 = SOP48-20-720B
U22 = BGA169-BGA153-0_5MM
U23 U24 = DFN2510P10E
X2 = X288

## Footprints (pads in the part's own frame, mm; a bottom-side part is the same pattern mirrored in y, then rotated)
BGA96-32-1609I
  round 0.356 smd: A1(-6,-3.2) A2(-6,-2.4) A3(-6,-1.6) A7(-6,1.6) A8(-6,2.4) A9(-6,3.2) B1(-5.2,-3.2) B2(-5.2,-2.4) B3(-5.2,-1.6) B7(-5.2,1.6) B8(-5.2,2.4) B9(-5.2,3.2) C1(-4.4,-3.2) C2(-4.4,-2.4) C3(-4.4,-1.6) C7(-4.4,1.6) C8(-4.4,2.4) C9(-4.4,3.2) D1(-3.6,-3.2) D2(-3.6,-2.4) D3(-3.6,-1.6) D7(-3.6,1.6) D8(-3.6,2.4) D9(-3.6,3.2) E1(-2.8,-3.2) E2(-2.8,-2.4) E3(-2.8,-1.6) E7(-2.8,1.6) E8(-2.8,2.4) E9(-2.8,3.2) F1(-2,-3.2) F2(-2,-2.4) F3(-2,-1.6) F7(-2,1.6) F8(-2,2.4) F9(-2,3.2) G1(-1.2,-3.2) G2(-1.2,-2.4) G3(-1.2,-1.6) G7(-1.2,1.6) G8(-1.2,2.4) G9(-1.2,3.2) H1(-0.4,-3.2) H2(-0.4,-2.4) H3(-0.4,-1.6) H7(-0.4,1.6) H8(-0.4,2.4) H9(-0.4,3.2) J1(0.4,-3.2) J2(0.4,-2.4) J3(0.4,-1.6) J7(0.4,1.6) J8(0.4,2.4) J9(0.4,3.2) K1(1.2,-3.2) K2(1.2,-2.4) K3(1.2,-1.6) K7(1.2,1.6) K8(1.2,2.4) K9(1.2,3.2) L1(2,-3.2) L2(2,-2.4) L3(2,-1.6) L7(2,1.6) L8(2,2.4) L9(2,3.2) M1(2.8,-3.2) M2(2.8,-2.4) M3(2.8,-1.6) M7(2.8,1.6) M8(2.8,2.4) M9(2.8,3.2) N1(3.6,-3.2) N2(3.6,-2.4) N3(3.6,-1.6) N7(3.6,1.6) N8(3.6,2.4) N9(3.6,3.2) P1(4.4,-3.2) P2(4.4,-2.4) P3(4.4,-1.6) P7(4.4,1.6) P8(4.4,2.4) P9(4.4,3.2) R1(5.2,-3.2) R2(5.2,-2.4) R3(5.2,-1.6) R7(5.2,1.6) R8(5.2,2.4) R9(5.2,3.2) T1(6,-3.2) T2(6,-2.4) T3(6,-1.6) T7(6,1.6) T8(6,2.4) T9(6,3.2)
BGA169-BGA153-0_5MM
  round 1.016 smd: 1(-12.413,-6.351) 2(14.506,0.734)
  round 0.254 smd: A4(-6.75,-1.75) A6(-6.75,-0.75) A9(-6.75,0.75) A11(-6.75,1.75) AA2(3.25,-2.75) AA3(3.25,-2.25) AA4(3.25,-1.75) AA5(3.25,-1.25) AA6(3.25,-0.75) AA7(3.25,-0.25) AA8(3.25,0.25) AA9(3.25,0.75) AA10(3.25,1.25) AA11(3.25,1.75) AA12(3.25,2.25) AA13(3.25,2.75) AA14(3.25,3.25) AE1(5.25,-3.25) AE14(5.25,3.25) AG2(6.25,-2.75) AG13(6.25,2.75) AH4(6.75,-1.75) AH6(6.75,-0.75) AH9(6.75,0.75) AH11(6.75,1.75) B2(-6.25,-2.75) B13(-6.25,2.75) D1(-5.25,-3.25) D14(-5.25,3.25) H8(-3.25,0.25) H9(-3.25,0.75) H10(-3.25,1.25) H11(-3.25,1.75) H12(-3.25,2.25) H13(-3.25,2.75) H14(-3.25,3.25) J2(-2.75,-2.75) J3(-2.75,-2.25) J4(-2.75,-1.75) J5(-2.75,-1.25) J6(-2.75,-0.75) J7(-2.75,-0.25) J8(-2.75,0.25) J9(-2.75,0.75) J10(-2.75,1.25) J11(-2.75,1.75) J12(-2.75,2.25) J13(-2.75,2.75) J14(-2.75,3.25) K2(-2.25,-2.75) K3(-2.25,-2.25) K4(-2.25,-1.75) K5(-2.25,-1.25) K6(-2.25,-0.75) K7(-2.25,-0.25) K8(-2.25,0.25) K9(-2.25,0.75) K10(-2.25,1.25) K11(-2.25,1.75) K12(-2.25,2.25) K13(-2.25,2.75) K14(-2.25,3.25) L2(-1.75,-2.75) L3(-1.75,-2.25) L4(-1.75,-1.75) L12(-1.75,2.25) L13(-1.75,2.75) L14(-1.75,3.25) M1(-1.25,-3.25) M2(-1.25,-2.75) M3(-1.25,-2.25) M5(-1.25,-1.25) M6(-1.25,-0.75) M7(-1.25,-0.25) M8(-1.25,0.25) M9(-1.25,0.75) M10(-1.25,1.25) M12(-1.25,2.25) M13(-1.25,2.75) M14(-1.25,3.25) N1(-0.75,-3.25) N2(-0.75,-2.75) N3(-0.75,-2.25) N5(-0.75,-1.25) N10(-0.75,1.25) N12(-0.75,2.25) N13(-0.75,2.75) N14(-0.75,3.25) P1(-0.25,-3.25) P2(-0.25,-2.75) P3(-0.25,-2.25) P5(-0.25,-1.25) P10(-0.25,1.25) P12(-0.25,2.25) P13(-0.25,2.75) P14(-0.25,3.25) R1(0.25,-3.25) R2(0.25,-2.75) R3(0.25,-2.25) R5(0.25,-1.25) R10(0.25,1.25) R12(0.25,2.25) R13(0.25,2.75) R14(0.25,3.25) T1(0.75,-3.25) T2(0.75,-2.75) T3(0.75,-2.25) T5(0.75,-1.25) T10(0.75,1.25) T12(0.75,2.25) T13(0.75,2.75) T14(0.75,3.25) U1(1.25,-3.25) U2(1.25,-2.75) U3(1.25,-2.25) U5(1.25,-1.25) U6(1.25,-0.75) U7(1.25,-0.25) U8(1.25,0.25) U9(1.25,0.75) U10(1.25,1.25) U12(1.25,2.25) U13(1.25,2.75) U14(1.25,3.25) V1(1.75,-3.25) V2(1.75,-2.75) V3(1.75,-2.25) V12(1.75,2.25) V13(1.75,2.75) V14(1.75,3.25) W1(2.25,-3.25) W2(2.25,-2.75) W3(2.25,-2.25) W4(2.25,-1.75) W5(2.25,-1.25) W6(2.25,-0.75) W7(2.25,-0.25) W8(2.25,0.25) W9(2.25,0.75) W10(2.25,1.25) W11(2.25,1.75) W12(2.25,2.25) W13(2.25,2.75) W14(2.25,3.25) Y2(2.75,-2.75) Y3(2.75,-2.25) Y4(2.75,-1.75) Y5(2.75,-1.25) Y6(2.75,-0.75) Y7(2.75,-0.25) Y8(2.75,0.25) Y9(2.75,0.75) Y10(2.75,1.25) Y11(2.75,1.75) Y12(2.75,2.25) Y13(2.75,2.75) Y14(2.75,3.25)
  oval 0.203x0.254 smd: AA1(3.25,-3.25) H1(-3.25,-3.25) J1(-2.75,-3.25) K1(-2.25,-3.25) L1(-1.75,-3.25) Y1(2.75,-3.25)
  oval 0.254x0.203 smd: H2(-3.25,-2.75) H3(-3.25,-2.25) H4(-3.25,-1.75) H5(-3.25,-1.25) H6(-3.25,-0.75) H7(-3.25,-0.25)
CDTWIFI
  rect 1.981x1.524 smd: 1(6.087,4.005) 5(6.087,-4.795)
  rect 1.981x1.321 smd: 2(6.087,1.505) 4(6.087,-1.995)
  rect 2.184x1.27 smd: 3(6.189,-0.245)
  rect 2.489x1.397 smd: 6(-6.341,4.5) 7(-6.341,2.5)
CDTWIFI10
  oval 2.54x1.397 smd: 1(-6.1,4.121) 2(-6.1,2.121) 3(-6.1,-0.856) 4(-6.1,-3.015)
  oval 2.032x1.397 smd: 5(6.1,3.621) 6(6.1,1.121) 7(6.1,-2.379) 8(6.1,-5.179)
  oval 1.397x2.54 smd: 9(3.654,-6.5) 10(2.384,-6.5)
DC-002
  oval 2.997x1.803 hole 1.524x0.813: 1(0,0) 2(0,5)
  oval 1.803x2.997 hole 0.813x1.524: 3(-2.7,2.8)
DFN2510P10E
  oval 0.254x0.813 smd: 1(-1,-0.525) 5(1,-0.525) 6(1,0.525) 10(-1,0.525)
  oval 0.229x0.813 smd: 2(-0.5,-0.525) 4(0.5,-0.525) 7(0.5,0.525) 9(-0.5,0.525)
  oval 0.356x0.813 smd: 3(0,-0.525) 8(0,0.525)
HOLE182-142
  round 4.623 hole 3.607: 1(0,0)
HSC0402
  rect 0.508x0.508 smd: 1(-0.406,0) 2(0.406,0)
HSCOX-AMC-TM-A
  rect 0.813x0.813 smd: 1(0,1.35)
  rect 1.168x2.184 smd: 2(-1.326,0) 3(1.326,0)
HSOD323A
  rect 1.118x0.508 smd: 1(1.372,0) 2(-1.372,0)
HSR0402
  rect 0.508x0.508 smd: 1(-0.406,0) 2(0.406,0)
ID-BOARD
  round 1.016 smd: 1(0,0)
LED3C-100C
  rect 1.524x1.524 hole 0.965: 1(0,0)
  round 1.524 hole 0.965: 2(2.54,0) 3(5.08,0)
LQFP216-040-2424
  rect 0.305x1.397 smd: 1(-10.65,-12.71) 54(10.65,-12.71) 109(10.65,12.71) 162(-10.65,12.71)
  rect 0.203x1.397 smd: 2(-10.2,-12.71) 3(-9.8,-12.71) 4(-9.4,-12.71) 5(-9,-12.71) 6(-8.6,-12.71) 7(-8.2,-12.71) 8(-7.8,-12.71) 9(-7.4,-12.71) 10(-7,-12.71) 11(-6.6,-12.71) 12(-6.2,-12.71) 13(-5.8,-12.71) 14(-5.4,-12.71) 15(-5,-12.71) 16(-4.6,-12.71) 17(-4.2,-12.71) 18(-3.8,-12.71) 19(-3.4,-12.71) 20(-3,-12.71) 21(-2.6,-12.71) 22(-2.2,-12.71) 23(-1.8,-12.71) 24(-1.4,-12.71) 25(-1,-12.71) 26(-0.6,-12.71) 27(-0.2,-12.71) 28(0.2,-12.71) 29(0.6,-12.71) 30(1,-12.71) 31(1.4,-12.71) 32(1.8,-12.71) 33(2.2,-12.71) 34(2.6,-12.71) 35(3,-12.71) 36(3.4,-12.71) 37(3.8,-12.71) 38(4.2,-12.71) 39(4.6,-12.71) 40(5,-12.71) 41(5.4,-12.71) 42(5.8,-12.71) 43(6.2,-12.71) 44(6.6,-12.71) 45(7,-12.71) 46(7.4,-12.71) 47(7.8,-12.71) 48(8.2,-12.71) 49(8.6,-12.71) 50(9,-12.71) 51(9.4,-12.71) 52(9.8,-12.71) 53(10.2,-12.71) 110(10.2,12.71) 111(9.8,12.71) 112(9.4,12.71) 113(9,12.71) 114(8.6,12.71) 115(8.2,12.71) 116(7.8,12.71) 117(7.4,12.71) 118(7,12.71) 119(6.6,12.71) 120(6.2,12.71) 121(5.8,12.71) 122(5.4,12.71) 123(5,12.71) 124(4.6,12.71) 125(4.2,12.71) 126(3.8,12.71) 127(3.4,12.71) 128(3,12.71) 129(2.6,12.71) 130(2.2,12.71) 131(1.8,12.71) 132(1.4,12.71) 133(1,12.71) 134(0.6,12.71) 135(0.2,12.71) 136(-0.2,12.71) 137(-0.6,12.71) 138(-1,12.71) 139(-1.4,12.71) 140(-1.8,12.71) 141(-2.2,12.71) 142(-2.6,12.71) 143(-3,12.71) 144(-3.4,12.71) 145(-3.8,12.71) 146(-4.2,12.71) 147(-4.6,12.71) 148(-5,12.71) 149(-5.4,12.71) 150(-5.8,12.71) 151(-6.2,12.71) 152(-6.6,12.71) 153(-7,12.71) 154(-7.4,12.71) 155(-7.8,12.71) 156(-8.2,12.71) 157(-8.6,12.71) 158(-9,12.71) 159(-9.4,12.71) 160(-9.8,12.71) 161(-10.2,12.71)
  rect 1.397x0.305 smd: 55(12.71,-10.65) 108(12.71,10.65) 163(-12.71,10.65) 216(-12.71,-10.65)
  rect 1.397x0.203 smd: 56(12.71,-10.2) 57(12.71,-9.8) 58(12.71,-9.4) 59(12.71,-9) 60(12.71,-8.6) 61(12.71,-8.2) 62(12.71,-7.8) 63(12.71,-7.4) 64(12.71,-7) 65(12.71,-6.6) 66(12.71,-6.2) 67(12.71,-5.8) 68(12.71,-5.4) 69(12.71,-5) 70(12.71,-4.6) 71(12.71,-4.2) 72(12.71,-3.8) 73(12.71,-3.4) 74(12.71,-3) 75(12.71,-2.6) 76(12.71,-2.2) 77(12.71,-1.8) 78(12.71,-1.4) 79(12.71,-1) 80(12.71,-0.6) 81(12.71,-0.2) 82(12.71,0.2) 83(12.71,0.6) 84(12.71,1) 85(12.71,1.4) 86(12.71,1.8) 87(12.71,2.2) 88(12.71,2.6) 89(12.71,3) 90(12.71,3.4) 91(12.71,3.8) 92(12.71,4.2) 93(12.71,4.6) 94(12.71,5) 95(12.71,5.4) 96(12.71,5.8) 97(12.71,6.2) 98(12.71,6.6) 99(12.71,7) 100(12.71,7.4) 101(12.71,7.8) 102(12.71,8.2) 103(12.71,8.6) 104(12.71,9) 105(12.71,9.4) 106(12.71,9.8) 107(12.71,10.2) 164(-12.71,10.2) 165(-12.71,9.8) 166(-12.71,9.4) 167(-12.71,9) 168(-12.71,8.6) 169(-12.71,8.2) 170(-12.71,7.8) 171(-12.71,7.4) 172(-12.71,7) 173(-12.71,6.6) 174(-12.71,6.2) 175(-12.71,5.8) 176(-12.71,5.4) 177(-12.71,5) 178(-12.71,4.6) 179(-12.71,4.2) 180(-12.71,3.8) 181(-12.71,3.4) 182(-12.71,3) 183(-12.71,2.6) 184(-12.71,2.2) 185(-12.71,1.8) 186(-12.71,1.4) 187(-12.71,1) 188(-12.71,0.6) 189(-12.71,0.2) 190(-12.71,-0.2) 191(-12.71,-0.6) 192(-12.71,-1) 193(-12.71,-1.4) 194(-12.71,-1.8) 195(-12.71,-2.2) 196(-12.71,-2.6) 197(-12.71,-3) 198(-12.71,-3.4) 199(-12.71,-3.8) 200(-12.71,-4.2) 201(-12.71,-4.6) 202(-12.71,-5) 203(-12.71,-5.4) 204(-12.71,-5.8) 205(-12.71,-6.2) 206(-12.71,-6.6) 207(-12.71,-7) 208(-12.71,-7.4) 209(-12.71,-7.8) 210(-12.71,-8.2) 211(-12.71,-8.6) 212(-12.71,-9) 213(-12.71,-9.4) 214(-12.71,-9.8) 215(-12.71,-10.2)
  rect 8.382x8.382 smd: 217(0,0)
MICRO_SD8-PUSH
  rect 0.813x1.27 smd: 1(2.9,-5.605) 2(1.8,-5.605) 3(0.7,-5.605) 4(-0.4,-5.605) 5(-1.5,-5.605) 6(-2.6,-5.605) 7(-3.7,-5.605) 8(-4.8,-5.605)
  rect 1.27x1.27 smd: 9(-6.74,-2.975) 10(-6.74,6.025)
  rect 1.524x1.143 smd: 11(-4.94,7.15) 12(2.84,7.15)
  rect 1.524x2.286 smd: 13(6.97,6.355) 15(-6.97,-5.125)
  rect 1.524x2.54 smd: 14(6.97,-4.975)
MJ8-RLY
  round 3.429 hole 3.429 unplated: (-2.794,2.54) (9.906,2.54)
  round 1.27 hole 0.914: 1(0,0) 2(1.016,-1.778) 3(2.032,0) 4(3.048,-1.778) 5(4.064,0) 6(5.08,-1.778) 7(6.096,0) 8(7.112,-1.778) 9(-3.302,-6.604) 10(-1.016,-6.604) 11(8.128,-6.604) 12(10.414,-6.604)
PWC3-RF-A
  rect 1.778x3.962 hole 0.762x2.946: 1(0,0)
  oval 3.454x1.778 hole 2.438x0.762: 2(2.3,4.8)
  oval 1.676x3.454 hole 0.66x2.438: 3(5.8,0)
RN8-0402
  rect 0.305x0.559 smd: 1(-0.762,-0.483) 4(0.762,-0.483) 5(0.762,0.483) 8(-0.762,0.483)
  rect 0.254x0.559 smd: 2(-0.254,-0.483) 3(0.254,-0.483) 6(0.254,0.483) 7(-0.254,0.483)
SAC6666
  rect 3.175x1.016 smd: 1(-2.5,0) 2(2.5,0)
SC0402
  rect 0.508x0.508 smd: 1(-0.406,0) 2(0.406,0)
SC0603
  rect 0.762x0.813 smd: 1(-0.699,0) 2(0.699,0)
SC0805
  rect 0.991x1.27 smd: 1(-0.813,0) 2(0.813,0)
SC1206
  rect 1.295x1.651 smd: 1(-1.346,0) 2(1.346,0)
SEN3-100C
  rect 1.27x1.27 hole 0.813: 1(-2.54,0)
  round 1.27 hole 0.813: 2(0,0) 3(2.54,0)
SGM8903
  rect 0.356x1.524 smd: 1(-1.95,-2.921) 2(-1.3,-2.921) 3(-0.65,-2.921) 4(0,-2.921) 5(0.65,-2.921) 6(1.3,-2.921) 7(1.95,-2.921) 8(1.95,2.921) 9(1.3,2.921) 10(0.65,2.921) 11(0,2.921) 12(-0.65,2.921) 13(-1.3,2.921) 14(-1.95,2.921)
SIP12-2_0MM-1827
  oval 3.175x1.524 hole 1.016: 1(-13.5,5.005) 2(-13.5,3.005) 3(-13.5,1.005) 4(-13.5,-0.995) 5(-13.5,-2.995) 6(-13.5,-4.995)
  oval 2.032x1.27 hole 1.016: 7(13.5,-5.604) 8(13.5,-4.104) 9(13.5,-2.604) 10(13.5,2.681) 11(13.5,4.181) 12(13.5,5.681)
SIP-1P
  round 1.651 hole 0.914: 1(0,0)
SL0402
  rect 0.483x0.508 smd: 1(-0.394,0) 2(0.394,0)
SL0603
  rect 0.711x0.813 smd: 1(-0.74,0) 2(0.74,0)
SL0805
  rect 0.94x1.27 smd: 1(-0.851,0) 2(0.851,0)
SOIC8N
  rect 0.635x1.905 smd: 1(-1.905,-2.6) 2(-0.635,-2.6) 3(0.635,-2.6) 4(1.905,-2.6) 5(1.905,2.6) 6(0.635,2.6) 7(-0.635,2.6) 8(-1.905,2.6)
  rect 3.505x2.616 smd: 9(0,0)
SOP48-20-720B
  rect 0.254x1.473 smd: 1(-5.75,-9.802) 2(-5.25,-9.802) 3(-4.75,-9.802) 4(-4.25,-9.802) 5(-3.75,-9.802) 6(-3.25,-9.802) 7(-2.75,-9.802) 8(-2.25,-9.802) 9(-1.75,-9.802) 10(-1.25,-9.802) 11(-0.75,-9.802) 12(-0.25,-9.802) 13(0.25,-9.802) 14(0.75,-9.802) 15(1.25,-9.802) 16(1.75,-9.802) 17(2.25,-9.802) 18(2.75,-9.802) 19(3.25,-9.802) 20(3.75,-9.802) 21(4.25,-9.802) 22(4.75,-9.802) 23(5.25,-9.802) 24(5.75,-9.802) 25(5.75,9.802) 26(5.25,9.802) 27(4.75,9.802) 28(4.25,9.802) 29(3.75,9.802) 30(3.25,9.802) 31(2.75,9.802) 32(2.25,9.802) 33(1.75,9.802) 34(1.25,9.802) 35(0.75,9.802) 36(0.25,9.802) 37(-0.25,9.802) 38(-0.75,9.802) 39(-1.25,9.802) 40(-1.75,9.802) 41(-2.25,9.802) 42(-2.75,9.802) 43(-3.25,9.802) 44(-3.75,9.802) 45(-4.25,9.802) 46(-4.75,9.802) 47(-5.25,9.802) 48(-5.75,9.802)
SOT23
  rect 1.016x1.27 smd: 1(-1.016,-1.143) 2(1.016,-1.143) 3(0,1.143)
SOT23-5
  rect 0.711x1.016 smd: 1(-0.95,-1.3) 2(0,-1.3) 3(0.95,-1.3) 4(0.95,1.3) 5(-0.95,1.3)
SOT23_5
  rect 0.635x1.27 smd: 1(-0.95,-1.2) 2(0,-1.2) 3(0.95,-1.2) 4(0.95,1.2) 5(-0.95,1.2)
SOT23_6
  rect 0.635x1.397 smd: 1(-0.95,-1.2) 2(0,-1.2) 3(0.95,-1.2) 4(0.95,1.2) 5(0,1.2) 6(-0.95,1.2)
SOT23A-6L
  rect 0.635x1.27 smd: 1(-0.95,-1.25) 2(0,-1.25) 3(0.95,-1.25) 4(0.95,1.25) 5(0,1.25) 6(-0.95,1.25)
SPSW6-T
  rect 1.829x1.118 smd: 1(-3.1,1.85) 2(3.1,1.85) 3(-3.1,-1.85) 4(3.1,-1.85)
  rect 1.397x0.61 smd: 5(0,2.5) 6(0,-2.5)
SR0402
  rect 0.508x0.508 smd: 1(-0.406,0) 2(0.406,0)
SR0603
  rect 0.711x0.813 smd: 1(-0.737,0) 2(0.737,0)
SR0805
  rect 0.838x1.143 smd: 1(-0.927,0) 2(0.927,0)
STFM16-50-285
  rect 0.635x1.905 smd: 1(-4.445,-4.381) 2(-3.175,-4.381) 3(-1.905,-4.381) 4(-0.635,-4.381) 5(0.635,-4.381) 6(1.905,-4.381) 7(3.175,-4.381) 8(4.445,-4.381) 9(4.445,4.381) 10(3.175,4.381) 11(1.905,4.381) 12(0.635,4.381) 13(-0.635,4.381) 14(-1.905,4.381) 15(-3.175,4.381) 16(-4.445,4.381)
SWPA4020S
  rect 1.905x3.683 smd: 1(-1.55,0) 2(1.55,0)
SWPA5040S
  rect 1.397x4.191 smd: 1(-1.85,0) 2(1.85,0)
TSW4-RG-C
  round 1.524 hole 1.016: 1(0,0) 2(4.5,0)
  round 2.032 hole 1.321: 3(-1.25,2.5) 4(5.75,2.5)
unnamed
  round 1.016 hole 1.016 unplated: (-3,1.13) (-1.5,1.13) (0,1.13) (1.5,1.13) (3,1.13)
unnamed#3
  round 2.032 hole 2.032 unplated: (0,0)
USB4-1415
  rect 1.27x1.905 hole 1.016: 1(0,0)
  oval 1.27x1.905 hole 1.016: 2(2.5,0) 3(4.5,0) 4(7,0)
  round 3.048 hole 2.286: 5(-3.07,-2.71) 6(10.07,-2.71)
VAF6-1107
  round 1.016 hole 1.016 unplated: (1.7,2.3) (8.5,2.3)
  rect 2.159x1.626 hole 1.321x0.61: 2(0,0)
  oval 2.159x1.626 hole 1.321x0.61: 3(3,0)
  oval 2.337x1.626 hole 1.321x0.61: 4(7,0.2) 5(8.6,4.6) 6(0,5.6)
WBC0104-49T
  oval 0.762x1.143 hole 0.508: 1(0,0) 2(1.25,0) 3(2.5,0) 4(3.75,0)
WBC0119-20R-A
  round 1.092 hole 1.092 unplated: (-2.5,2.745) (2.5,2.745)
  rect 0.254x2.591 smd: 1(4.5,5.155) 2(4,5.155) 3(3.5,5.155) 4(3,5.155) 5(2.5,5.155) 6(2,5.155) 7(1.5,5.155) 8(1,5.155) 9(0.5,5.155) 10(0,5.155) 11(-0.5,5.155) 12(-1,5.155) 13(-1.5,5.155) 14(-2,5.155) 15(-2.5,5.155) 16(-3,5.155) 17(-3.5,5.155) 18(-4,5.155) 19(-4.5,5.155)
  oval 1.524x3.302 hole 0.914x2.667: 20(-7.25,4.395) 21(7.25,4.395)
  oval 1.524x2.794 hole 0.914x2.083: 22(-7.25,-1.565) 23(7.25,-1.565)
X288
  rect 1.651x1.27 smd: 1(-1.15,-0.85) 2(1.15,-0.85) 3(1.15,0.85) 4(-1.15,0.85)

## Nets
1V1_CORE: C1.1 C19.1 C34.1 C37.1 C51.1 C62.1 C64.1 C66.1 C70.1 C73.1 C82.2 C90.1 C107.1 C120.1 C121.1 C126.1 C127.1 C128.1 C129.1 C130.1 C189.1 C193.1 C282.1 L3.2 LB12.2 LB21.1 LB31.1 R101.2 U1.4 U1.10 U1.30 U1.39 U1.49 U1.78 U1.86 U1.105 U1.118 U1.134 U1.158 U1.168 U1.180 U1.186 U1.193 U1.202 U1.214
1V1_CPU: C15.1 C16.1 C28.1 C31.1 C35.1 C41.1 C42.1 C75.1 C76.2 C81.1 C89.1 C116.1 C132.1 C134.1 C242.1 C243.1 C257.1 L2.2 R53.2 U1.91 U1.92 U1.93 U1.95 U1.96 U1.98
1V5_DDR3: C20.1 C40.1 C48.1 C49.1 C52.1 C68.1 C84.2 C92.1 C94.1 C96.1 C97.1 C98.1 C99.1 C100.1 C101.1 C102.1 C103.1 C104.1 C109.1 C110.1 C117.1 C125.1 C137.1 C201.1 C202.1 C203.1 C204.1 C205.1 C206.1 C208.1 C209.1 C210.1 C211.1 C212.1 C213.1 C214.1 C215.1 C216.1 C218.1 C219.1 C220.1 C221.1 C223.1 C224.1 C225.1 C226.1 C227.1 C228.1 C229.1 C230.1 C231.1 C232.1 C233.1 C234.1 C235.1 C236.1 C237.1 C238.1 C239.1 C240.1 C258.1 C315.1 C319.1 L4.2 R10.2 R54.1 R60.1 R78.1 R92.1 U1.1 U1.7 U1.13 U1.16 U1.25 U1.35 U1.44 U1.53 U1.165 U1.171 U1.174 U1.183 U1.190 U1.196 U1.199 U1.205 U1.208 U3.A1 U3.A8 U3.B2 U3.C1 U3.C9 U3.D2 U3.D9 U3.E9 U3.F1 U3.G7 U3.H2 U3.H9 U3.K2 U3.K8 U3.N1 U3.N9 U3.R1 U3.R9 U6.A1 U6.A8 U6.B2 U6.C1 U6.C9 U6.D2 U6.D9 U6.E9 U6.F1 U6.G7 U6.H2 U6.H9 U6.K2 U6.K8 U6.N1 U6.N9 U6.R1 U6.R9
3V3: C2.1 C4.1 C13.1 C25.1 C26.1 C27.1 C39.1 C46.1 C53.1 C67.1 C69.1 C91.1 C108.1 C114.1 J18.4 L5.2 Q13.2 R2.1 R6.1 R31.1 R34.1 R88.2 R105.2 R135.1 R136.1 R140.2 R178.2 U1.65 U11.4 U13.4 U15.4
3V3_MOS: C74.1 C131.1 C197.1 C198.1 C199.1 C245.1 C283.1 D2.2 D9.2 D19.2 J25.10 J25.12 LB1.2 LB4.2 LB7.2 LB8.2 LB14.1 LB17.1 LB20.1 LB22.1 Q13.3 Q15.2 R25.1 R26.1 R30.1 R39.2 R41.2 R77.1 R86.1 R94.1 R155.1 U1.74 U1.83 U1.104 U1.120
3V3_MOS_FLASH: C36.1 C63.1 C88.1 C93.1 C105.1 C142.1 C143.1 C275.1 C323.1 C324.1 D2.1 R12.1 R29.1 R58.1 R68.2 R80.1 R94.2 R96.2 R176.1 R177.1 R188.1 R189.1 R202.1 R203.1 R212.1 R215.1 U19.1 U19.12 U19.24 U19.34 U19.37 U22.AA3 U22.AA5 U22.K6 U22.M6 U22.N5 U22.T10 U22.U9 U22.W4 U22.Y4
3V3_SD: C263.1 C391.1 J21.4 Q15.3 R86.2 R210.1
3V3_WIFI: C21.1 C106.1 J2.5 LB4.1 U2.5 U7.8
5V0: C6.1 C58.1 C59.1 C111.1 C112.1 D4.2 J1.1 J10.1 Q14.2 R4.1 R144.1 U14.2
5V0_MOS: C56.1 C119.1 D20.2 LB2.2 LB3.2 Q14.3 R11.2 R15.2 R179.1 U10.1 U12.1
5V0_MOS_HDMI: C150.1 D20.1 J26.18 R186.2 R187.2 U4.5
AVDD11_PLL012: C12.1 C185.1 LB21.2 U1.68
AVDD33_PLL01: C14.1 C186.1 LB22.2 U1.66
AVDD33_USB2: C3.1 C95.1 LB17.2 U1.88
GND: C1.2 C2.2 C3.2 C4.2 C5.2 C7.2 C8.2 C9.2 C10.2 C11.2 C12.2 C13.2 C14.2 C15.2 C16.2 C17.2 C18.2 C19.2 C20.2 C21.2 C22.2 C23.2 C24.2 C25.2 C26.2 C27.2 C28.2 C29.2 C30.2 C31.2 C33.1 C34.2 C35.2 C36.2 C37.2 C38.2 C39.2 C40.2 C41.2 C42.2 C44.2 C46.2 C47.2 C48.2 C49.2 C50.2 C51.2 C52.2 C53.2 C56.2 C57.2 C58.2 C59.2 C60.2 C61.2 C62.2 C63.2 C64.2 C66.2 C67.2 C68.2 C69.2 C70.2 C71.2 C72.2 C73.2 C74.2 C75.2 C77.2 C78.2 C79.2 C81.2 C85.2 C86.2 C87.2 C88.2 C89.2 C90.2 C91.2 C92.2 C93.2 C94.2 C95.2 C96.2 C97.2 C98.2 C99.2 C101.2 C102.2 C104.2 C105.2 C106.2 C107.2 C108.2 C109.2 C110.2 C111.2 C112.2 C113.2 C114.2 C115.2 C116.2 C117.2 C118.2 C119.2 C120.2 C121.2 C122.2 C123.2 C124.2 C125.2 C126.2 C127.2 C128.2 C129.2 C130.2 C132.2 C134.2 C135.2 C136.2 C137.2 C138.1 C139.2 C140.2 C141.2 C142.2 C143.2 C149.2 C150.2 C153.2 C154.2 C158.2 C164.2 C177.2 C182.2 C185.2 C186.2 C189.2 C193.2 C197.2 C198.2 C199.2 C201.2 C202.2 C203.2 C204.2 C205.2 C206.2 C209.2 C210.2 C211.2 C212.2 C213.2 C214.2 C215.2 C216.2 C218.2 C219.2 C220.2 C221.2 C224.2 C225.2 C226.2 C227.2 C228.2 C229.2 C230.2 C231.2 C232.2 C233.2 C234.2 C235.2 C236.2 C237.2 C238.2 C239.2 C240.2 C242.2 C243.2 C245.2 C248.2 C250.1 C255.1 C257.2 C258.2 C263.2 C264.2 C270.2 C271.2 C275.2 C281.2 C282.2 C283.2 C297.2 C307.2 C308.2 C313.2 C314.2 C315.2 C316.2 C317.2 C319.2 C320.2 C323.2 C324.2 C334.2 C336.2 C339.2 C363.2 C364.2 C365.2 C391.2 D1.2 D3.2 D6.2 D9.1 J1.2 J1.3 J2.2 J2.7 J2.9 J2.10 J2.12 J3.1 J4.2 J4.3 J5.2 J5.3 J10.2 J10.3 J12.4 J12.5 J12.6 J13.4 J13.5 J13.6 J18.1 J21.6 J21.10 J21.11 J21.12 J21.13 J21.14 J21.15 J26.2 J26.5 J26.8 J26.11 J26.17 J26.20 J26.21 J26.22 J26.23 J34.5 LED1.2 Q1.2 Q2.2 Q4.2 Q5.2 R8.1 R9.2 R13.1 R24.1 R32.1 R33.2 R38.1 R40.2 R43.2 R45.2 R46.1 R47.1 R48.1 R50.2 R51.2 R52.2 R55.2 R56.1 R57.2 R71.1 R75.2 R82.1 R84.2 R85.1 R87.1 R89.2 R93.2 R96.1 R99.1 R100.2 R104.2 R145.2 R146.2 R149.2 R173.2 R183.2 R210.2 S1.1 S1.3 S1.4 S2.3 S2.4 S2.5 S2.6 U1.19 U1.62 U1.67 U1.94 U1.97 U1.110 U1.115 U1.177 U1.211 U1.217 U2.1 U2.6 U3.A9 U3.B1 U3.B3 U3.B9 U3.D1 U3.D8 U3.E1 U3.E2 U3.E8 U3.F9 U3.G1 U3.G8 U3.G9 U3.J2 U3.J8 U3.M1 U3.M9 U3.P1 U3.P9 U3.T1 U3.T9 U4.2 U5.1 U5.4 U5.10 U5.14 U6.A9 U6.B1 U6.B3 U6.B9 U6.D1 U6.D8 U6.E1 U6.E2 U6.E8 U6.F9 U6.G1 U6.G8 U6.G9 U6.J2 U6.J8 U6.M1 U6.M9 U6.P1 U6.P9 U6.T1 U6.T9 U7.1 U7.5 U10.2 U11.2 U12.2 U13.2 U14.4 U14.9 U15.2 U19.2 U19.13 U19.23 U19.25 U19.36 U19.48 U22.AA4 U22.AA6 U22.K4 U22.M7 U22.P5 U22.R10 U22.U8 U22.Y2 U22.Y5 U23.3 U23.8 U24.3 U24.8 X2.2 X2.4
VDD_AUDIO: C158.1 C320.1 R66.2 R91.1 R179.2 U5.9
ADAC_VOUTL: C350.2 R50.1 U1.114
ADAC_VOUTR: C351.1 R183.1 U1.116
AUDIO_L: C339.1 J34.3 R72.2
AUDIO_R: C140.1 J34.2 R74.1
CORE_CTRL: R23.2 U1.106
CPU_CTRL: R21.2 U1.107
CVBS: C79.1 C80.1 L6.1 R9.1 U1.109
CVBS_OUT: C17.1 C80.2 D9.3 J34.4 L6.2
DDR_ADDR0: U1.37 U3.N3 U6.N3
DDR_ADDR1: U1.32 U3.P7 U6.P7
DDR_ADDR2: U1.45 U3.P3 U6.P3
DDR_ADDR3: U1.43 U3.N2 U6.N2
DDR_ADDR4: U1.36 U3.P8 U6.P8
DDR_ADDR5: U1.46 U3.P2 U6.P2
DDR_ADDR6: U1.28 U3.R8 U6.R8
DDR_ADDR7: U1.42 U3.R2 U6.R2
DDR_ADDR8: U1.29 U3.T8 U6.T8
DDR_ADDR9: U1.51 U3.R3 U6.R3
DDR_ADDR10: U1.22 U3.L7 U6.L7
DDR_ADDR11: U1.23 U3.R7 U6.R7
DDR_ADDR12: U1.27 U3.N7 U6.N7
DDR_ADDR13: U1.50 U3.T3 U6.T3
DDR_ADDR14: U1.31 U3.T7 U6.T7
DDR_ADDR15: U1.26 U3.M7 U6.M7
DDR_BA0: U1.47 U3.M2 U6.M2
DDR_BA1: U1.24 U3.N8 U6.N8
DDR_BA2: U1.33 U3.M3 U6.M3
DDR_CASN: U1.40 U3.K3 U6.K3
DDR_CKE: R38.2 U1.21 U3.K9 U6.K9
DDR_CLK0N: R16.2 R17.2 R35.1 U3.K7 U6.K7
DDR_CLK0P: R16.1 R17.1 R18.1 U3.J7 U6.J7
DDR_CSN: U1.34 U3.L2 U6.L2
DDR_DM0: U1.181 U3.E7
DDR_DM1: U1.182 U3.D3
DDR_DM2: U1.215 U6.E7
DDR_DM3: U1.216 U6.D3
DDR_DQ0: U1.167 U3.E3
DDR_DQ1: U1.191 U3.F7
DDR_DQ2: U1.164 U3.F2
DDR_DQ3: U1.192 U3.F8
DDR_DQ4: U1.166 U3.H3
DDR_DQ5: U1.195 U3.H8
DDR_DQ6: U1.163 U3.G2
DDR_DQ7: U1.194 U3.H7
DDR_DQ8: U1.184 U3.D7
DDR_DQ9: U1.170 U3.C3
DDR_DQ10: U1.185 U3.C8
DDR_DQ11: U1.169 U3.C2
DDR_DQ12: U1.188 U3.A7
DDR_DQ13: U1.172 U3.A2
DDR_DQ14: U1.189 U3.B8
DDR_DQ15: U1.173 U3.A3
DDR_DQ16: U1.201 U6.E3
DDR_DQ17: U1.8 U6.F7
DDR_DQ18: U1.198 U6.F2
DDR_DQ19: U1.9 U6.F8
DDR_DQ20: U1.200 U6.H3
DDR_DQ21: U1.12 U6.H8
DDR_DQ22: U1.197 U6.G2
DDR_DQ23: U1.11 U6.H7
DDR_DQ24: U1.6 U6.D7
DDR_DQ25: U1.204 U6.C3
DDR_DQ26: U1.5 U6.C8
DDR_DQ27: U1.203 U6.C2
DDR_DQ28: U1.2 U6.A7
DDR_DQ29: U1.206 U6.A2
DDR_DQ30: U1.3 U6.B8
DDR_DQ31: U1.207 U6.A3
DDR_DQS0N: U1.176 U3.G3
DDR_DQS0P: U1.175 U3.F3
DDR_DQS1N: U1.179 U3.B7
DDR_DQS1P: U1.178 U3.C7
DDR_DQS2N: U1.210 U6.G3
DDR_DQS2P: U1.209 U6.F3
DDR_DQS3N: U1.213 U6.B7
DDR_DQS3P: U1.212 U6.C7
DDR_ODT: U1.48 U3.K1 U6.K1
DDR_PLL: C11.1 C264.1 C270.1 LB7.1 U1.20 U1.187
DDR_RASN: U1.52 U3.J3 U6.J3
DDR_RESETN: C313.1 C314.1 U1.38 U3.T2 U6.T2
DDR_VREF_A_CA: C86.1 C100.2 R55.1 R60.2 U3.M8
DDR_VREF_A_DQ: C208.2 C271.1 R54.2 R75.1 U3.H1
DDR_VREF_B_CA: C87.1 C103.2 R92.2 R93.1 U6.M8
DDR_VREF_B_DQ: C223.2 C308.1 R78.2 R84.1 U6.H1
DDR_WEN: U1.41 U3.L3 U6.L3
FE_1V1: C248.1 U1.147
FE_3V3: C7.1 C18.1 LB8.1 U1.144 U1.148
HDMI_TX0N: J26.9 U1.126 U24.2 U24.9
HDMI_TX0P: J26.7 U1.127 U24.1 U24.10
HDMI_TX1N: J26.6 U1.130 U23.5 U23.6
HDMI_TX1P: J26.4 U1.131 U23.4 U23.7
HDMI_TX2N: J26.3 U1.132 U23.2 U23.9
HDMI_TX2P: J26.1 U1.133 U23.1 U23.10
HDMI_TX_1V1: C78.1 C113.1 C164.1 C281.1 LB12.1 U1.128
HDMI_TX_3V3: C57.1 C77.1 LB1.1 U1.129
HDMI_TX_CEC: J26.13 R268.2 U1.123 U4.3
HDMI_TX_HOTPLUG: C149.1 J26.19 R8.2 U1.119 U4.4
HDMI_TX_SCL: J26.15 R186.1 U1.122 U4.1
HDMI_TX_SDA: J26.16 R187.1 U1.121 U4.6
HDMI_TXCN: J26.12 U1.124 U24.5 U24.6
HDMI_TXCP: J26.10 U1.125 U24.4 U24.7
IR_IN: D3.1 R140.1 U1.58
LED0_BASE: R26.2 R67.2 U1.151
LED0_LINK_ACT: R30.2 R79.2 U1.150
LED_CTRL: R3.1 R31.2 R51.1 U1.57
LED_GREEN: LED1.3 Q2.3 R34.2
LED_RED: LED1.1 Q1.3 R2.2 R22.1
NF_ALE_EMMC_PWREN: U1.80 U19.17
NF_CLE: U1.81 U19.16
NF_CSN0_EMMC_CMD: R212.2 U1.82 U19.9 U22.W5
NF_DQ0_EMMC_D0: R189.2 U1.77 U19.29 U22.H3
NF_DQ1_EMMC_D1: R12.2 U1.76 U19.30 U22.H4
NF_DQ2_EMMC_D2: R29.2 U1.75 U19.31 U22.H5
NF_DQ3_EMMC_D3: R58.2 U1.73 U19.32 U22.J2
NF_DQ4_EMMC_D4: R176.2 U1.72 U19.41 U22.J3
NF_DQ5_EMMC_D5: R177.2 U1.71 U19.42 U22.J4
NF_DQ6_EMMC_D6: R188.2 U1.70 U19.43 U22.J5
NF_DQ7_EMMC_D7_BOOT_SEL0: R33.1 R202.2 U1.69 U19.44 U22.J6
NF_RDY0_EMMC_RST: C115.1 R203.2 U1.85 U19.7 U22.U5
NF_REN_EMMC_CLK: R59.1 U19.8 U22.W6
NF_WEN_EMMC_DET: R56.2 U1.79 U19.18
NF_WP: R89.1 R215.2 U19.19
PWR_OFF/ON: R40.1 R41.1 U1.102
RECOVERY: C138.2 R25.2 S1.2 U1.103
RF0: C135.1 L1.2 U7.3
RF1: C50.1 L7.2 U2.7 U7.2
RFF0: C61.1 J5.1 L1.1
RFF1: C60.1 J4.1 L7.1
RX+_PHY0: R63.1 U1.143 U8.3 U8.6
RX-_PHY0: R64.1 U1.142 U8.4 U8.5
SDIO0_CARD_DETECT: J21.9 R155.2 U1.161
SDIO0_CCLK_OUT: J21.5 R5.2
SDIO0_CCMD: J21.3 R153.2 U1.157
SDIO0_CDATA0: J21.7 R152.2 U1.154
SDIO0_CDATA1: J21.8 R151.2 U1.153
SDIO0_CDATA2: J21.1 R156.2 U1.160
SDIO0_CDATA3: J21.2 R154.2 U1.159
SDIO0_CWPR: R43.1 U1.152
SDIO0_PWREN: R76.1 R149.1 U1.162
SDIO_3318: C22.1 R151.1 R152.1 R153.1 R154.1 R156.1 U1.155
SPDIF_OUT_BOOT_SEL1: R39.1 U1.117
STANDBY_PWROFF: R44.1 R73.1 R81.1 R88.1 R98.1 U1.59
TX+_PHY0: R61.1 U1.146 U8.1 U8.8
TX-_PHY0: R62.1 U1.145 U8.2 U8.7
UART0_RXD: J18.2 R136.2 U1.60
UART0_TXD: J18.3 R135.2 U1.61
USB0_DM: C141.1 D6.1 J12.2 U1.140
USB0_DP: C139.1 D1.1 J12.3 U1.141
USB01_1V1: C334.1 C336.1 LB31.2 U1.137
USB01_3V3: C10.1 C182.1 LB20.2 U1.139
USB1_DM: J2.4 U1.135 U2.4 U7.7
USB1_DP: J2.3 U1.136 U2.2 U7.6
USB2_DM: J13.2 U1.89
USB2_DP: J13.3 U1.90
USB_BOOT: R42.2 U1.108
VDAC_3V3: C9.1 C85.1 LB14.2 U1.112
XIN: C364.1 R1.2 U1.63 X2.1
XOUT: R1.1 R14.1 U1.64
$4N774: C71.1 R7.2 R21.1
$4N775: C76.1 R53.1 R70.1 R99.2 U11.6
$4N777: L2.1 U11.3
$4N782: C8.1 R73.2 U11.1
$4N811: C82.1 R13.2 R101.1 R110.1 U13.6
$4N812: C72.1 R23.1 R102.2
$4N813: R102.1 R110.2
$4N814: L3.1 U13.3
$4N818: C5.1 R81.2 U13.1
$4N881: C84.1 R10.1 R52.1 U15.5
$4N882: L4.1 U15.3
$4N883: C30.1 R6.2 R44.2 U15.1
$4N953: R100.1 R105.1 U14.5
$4N955: D4.1 R95.1 U14.1
$4N956: C83.2 R104.1
$4N957: C24.1 C83.1 U14.6
$4N958: R4.2 U14.7
$4N975: C44.1 U14.8
$4N980: C65.1 R95.2
$4N983: C65.2 L5.1 U14.3
$4N998: R7.1 R70.2
$5N541: Q4.3 R118.2 R144.2
$5N542: C6.2 Q13.1 Q14.1 R118.1
$5N549: Q4.1 R98.2
$6N1407: R173.1 U1.149
$6N2392: R59.2 U1.84
$6N2441: R5.1 U1.156
$6N2475: R82.2 R85.2 U1.138
$6N2516: C136.1 R42.1 S2.1 S2.2
$6N2574: C365.1 R14.2 X2.3
$7N1997: R24.2 R87.2 U1.87
$7N2001: R32.2 U1.111
$7N2021: C250.2 U1.113
$8N1926: R18.2 U1.17
$8N1927: R35.2 U1.18
$8N1992: R45.1 U1.54
$9N2491: C255.2 U1.55
$10N1177: R46.2 U3.L8
$11N1382: R71.2 U6.L8
$12N1699: R80.2 U19.38
$12N1717: R68.1 U19.39
$12N1720: C123.1 C124.1 U22.K2
$13N791: C38.1 C118.1 J13.1 LB3.1 U12.5
$13N792: C29.1 C122.1 J12.1 LB2.1 U10.5
$13N808: R15.1 U10.3
$13N809: R48.2 U10.4
$13N815: R11.1 U12.3
$13N860: R47.2 U12.4
$14N750: C47.1 C177.1 D3.3 R178.1
$14N753: Q5.1 R76.2
$14N755: Q5.3 R267.2
$14N770: C131.2 Q15.1 R77.2 R267.1
$14N801: Q2.1 R22.2
$14N806: Q1.1 R3.2
$15N1014: R49.1 U5.11
$15N1015: C350.1 R194.2
$15N1016: C316.1 R20.2 R28.2 R194.1
$15N1019: C54.2 R28.1 U5.13
$15N1039: C351.2 R193.1
$15N1040: C55.1 R27.2 U5.2
$15N1043: C317.1 R19.1 R27.1 R193.2
$15N1047: C55.2 R19.2 R74.2 R146.1 U5.3
$15N1073: C33.2 U5.6
$15N1074: C32.1 U5.7
$15N1075: C32.2 U5.8
$15N1098: C54.1 R20.1 R72.1 R145.1 U5.12
$15N1099: R49.2 R57.1 R91.2
$15N1107: C363.1 R66.1 U5.5
$16N1155: C154.1 C297.1 T2.7
$16N1157: J25.9 R67.1
